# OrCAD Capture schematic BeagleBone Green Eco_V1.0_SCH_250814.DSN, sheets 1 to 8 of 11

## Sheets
1 P02_Block Diagram: rev: V1.0
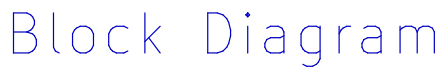
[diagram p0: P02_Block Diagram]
2 P01_Title, Revision History
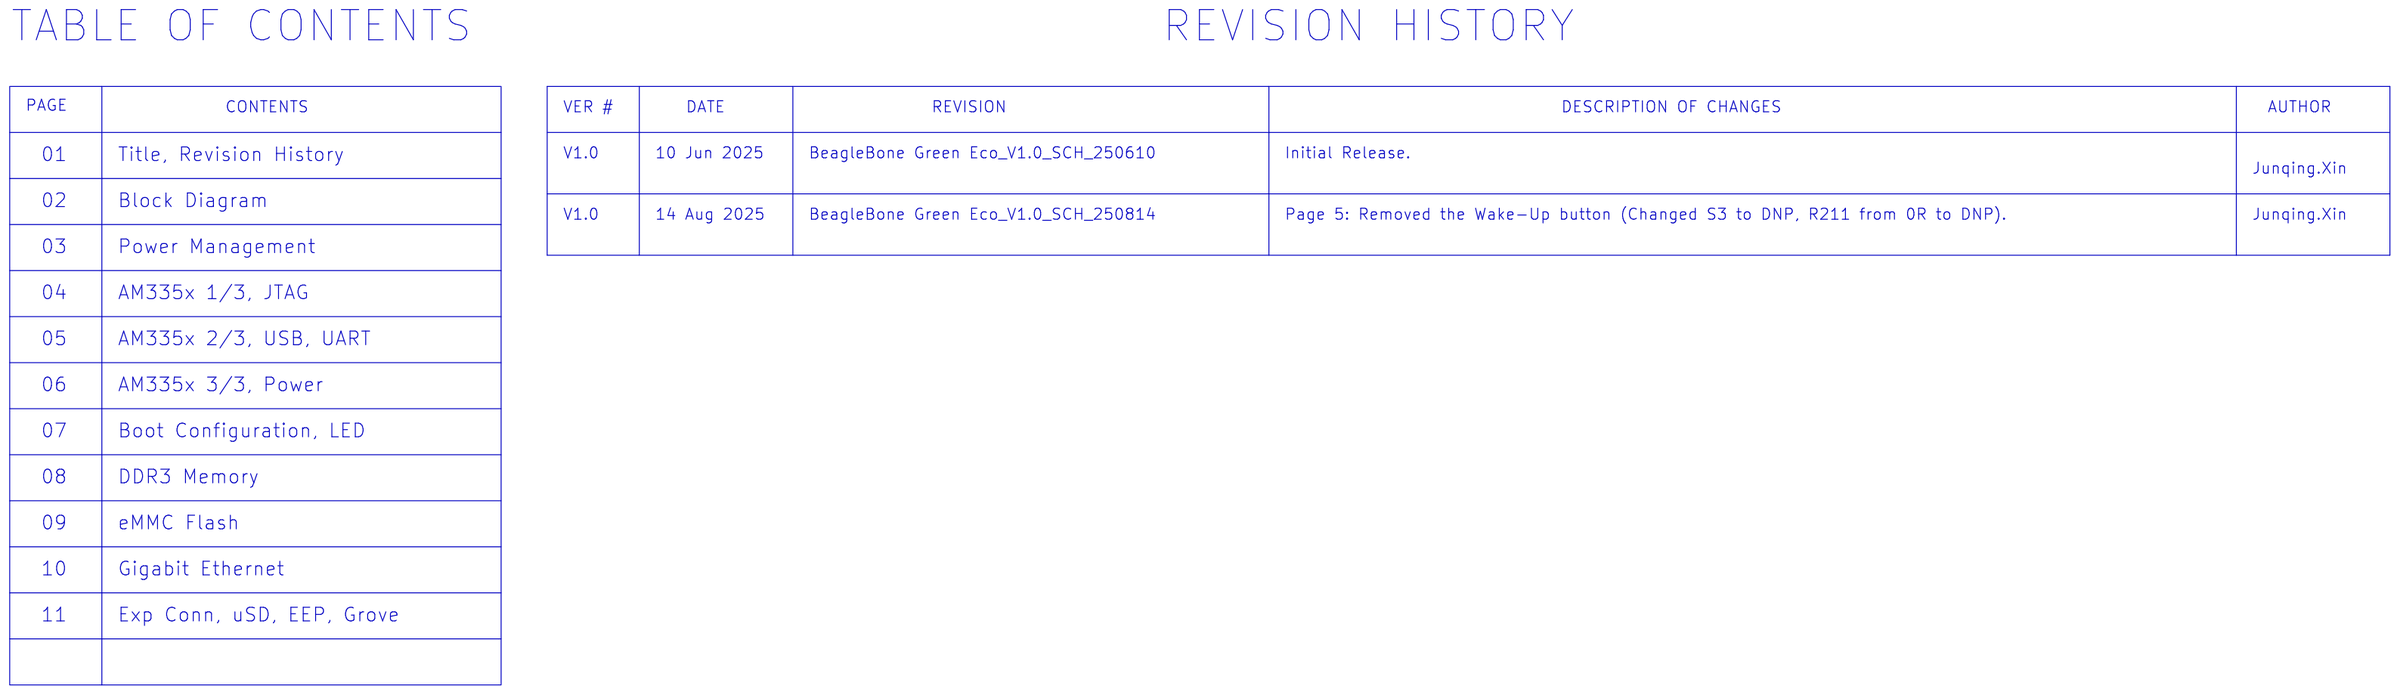
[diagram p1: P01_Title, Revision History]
3 P03_Power Management: size A3
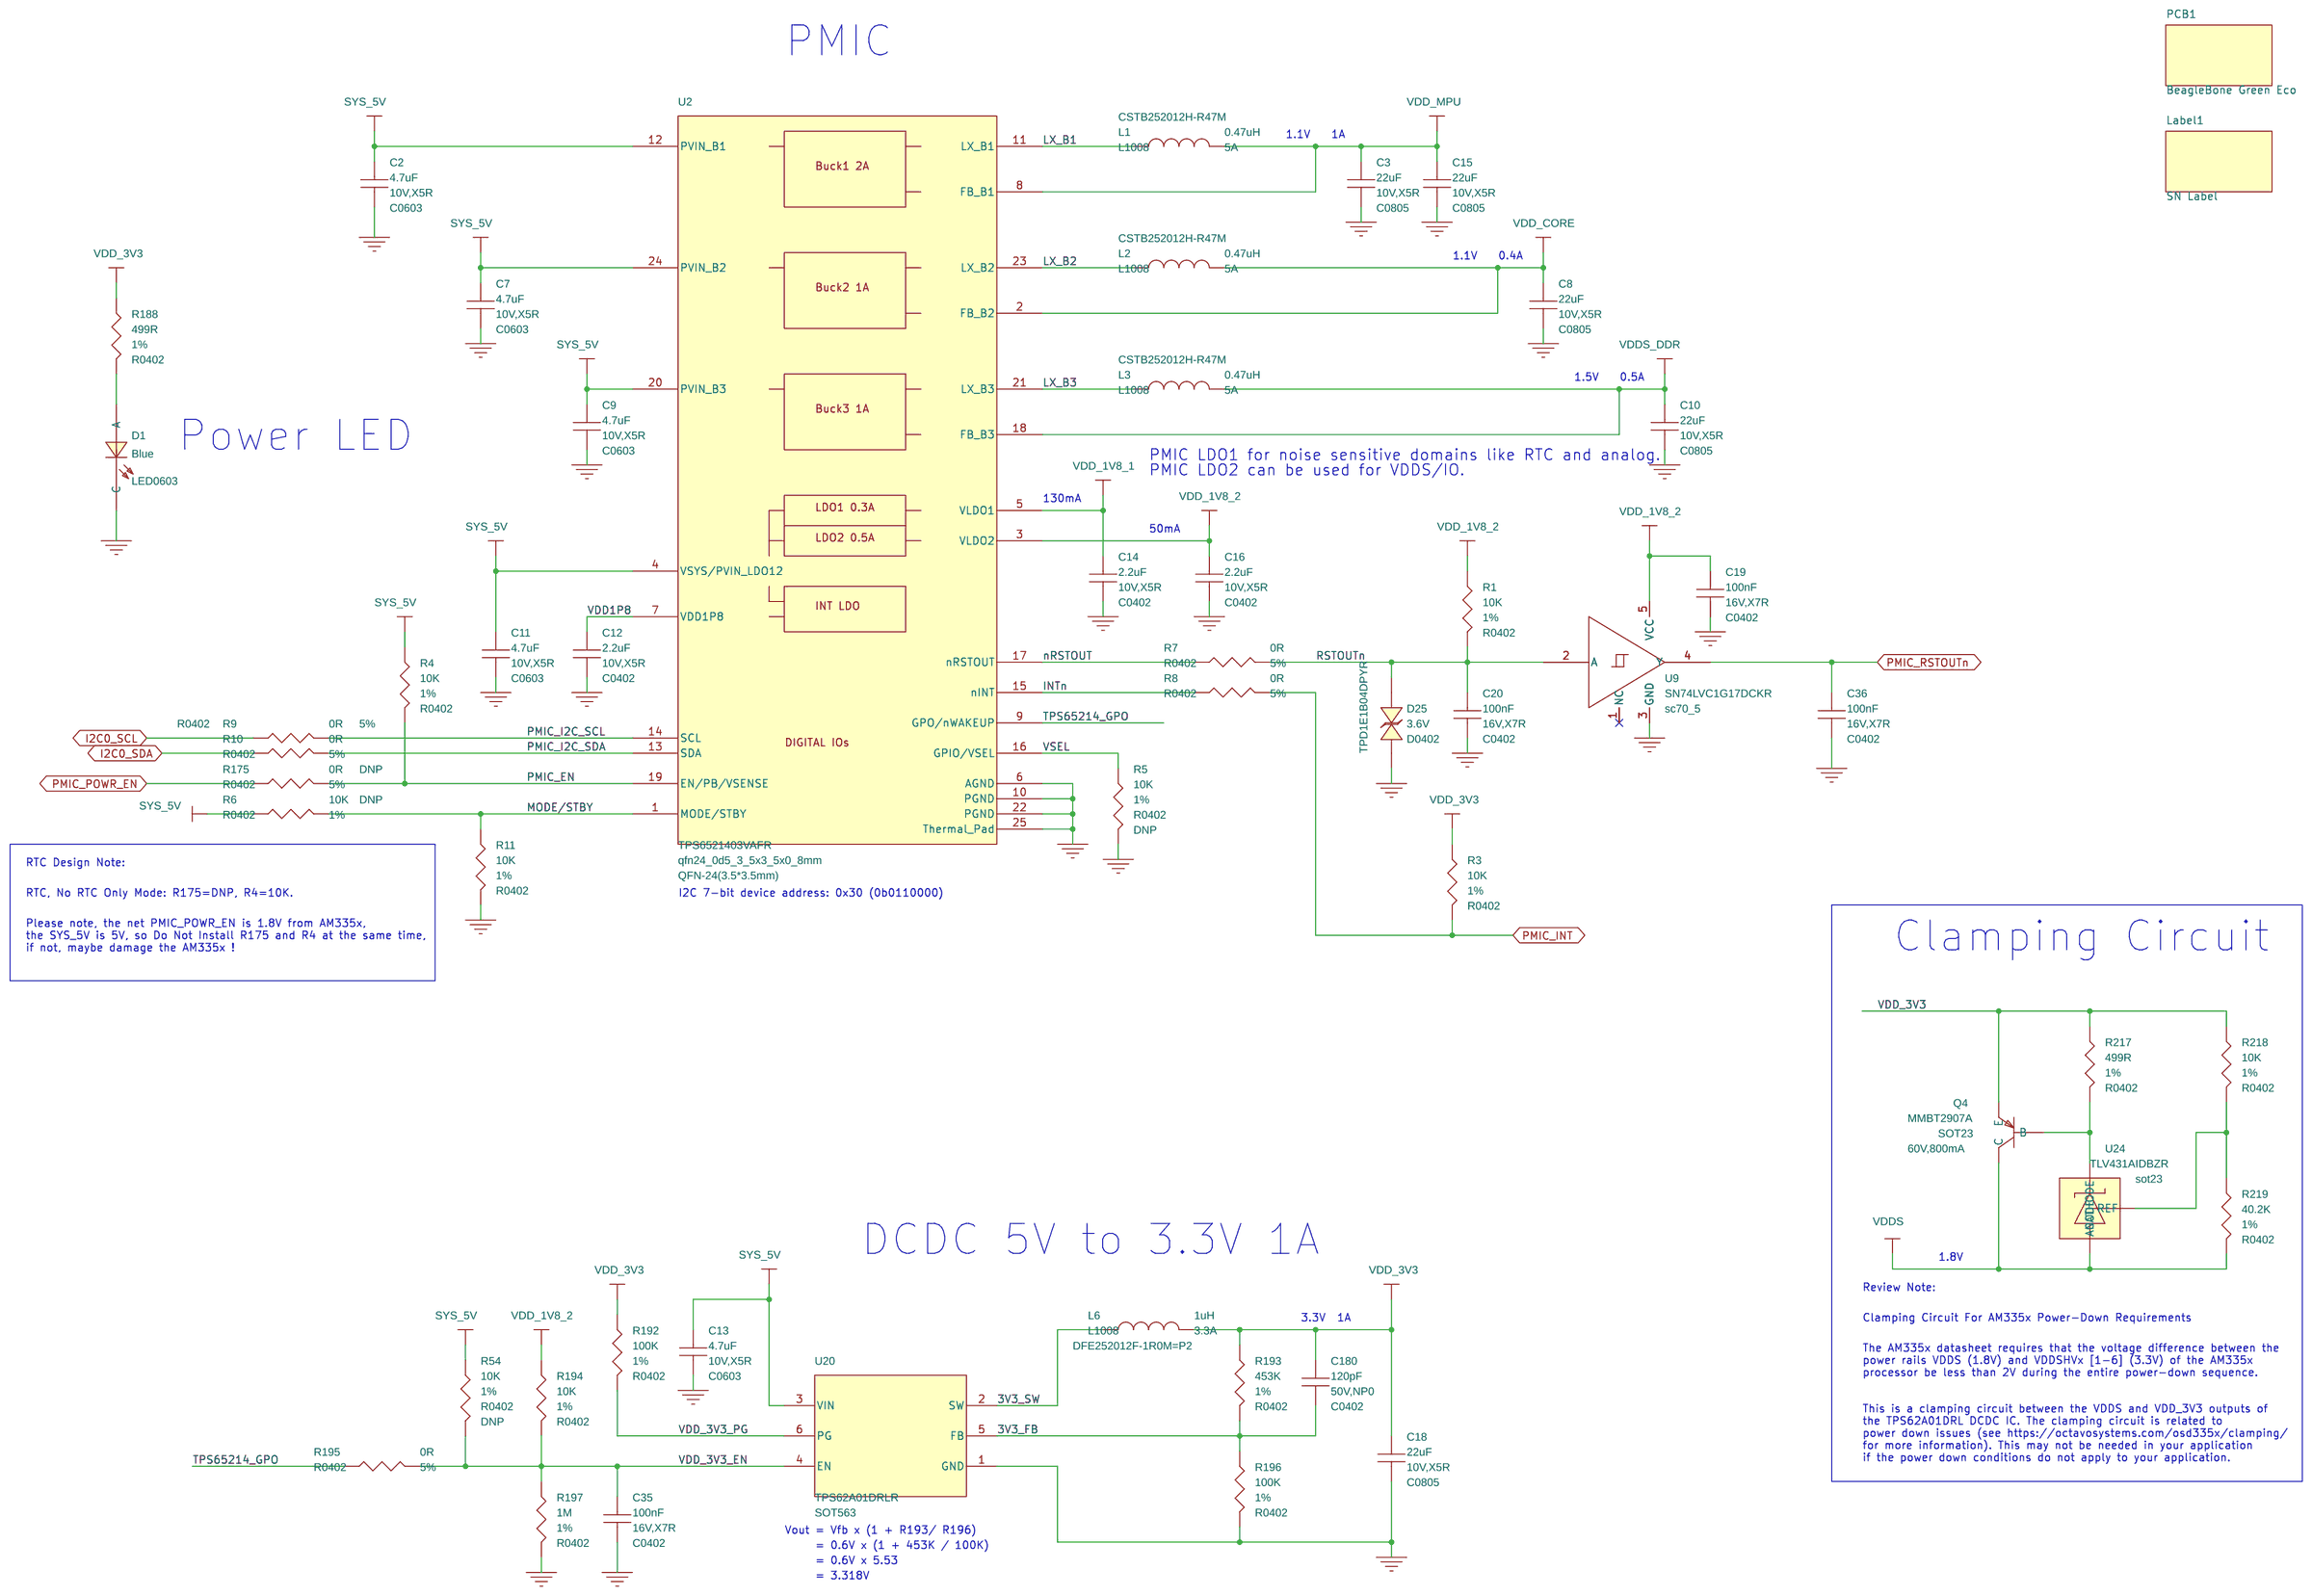
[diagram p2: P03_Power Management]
4 P07_Boot Configuration, LED: size A3
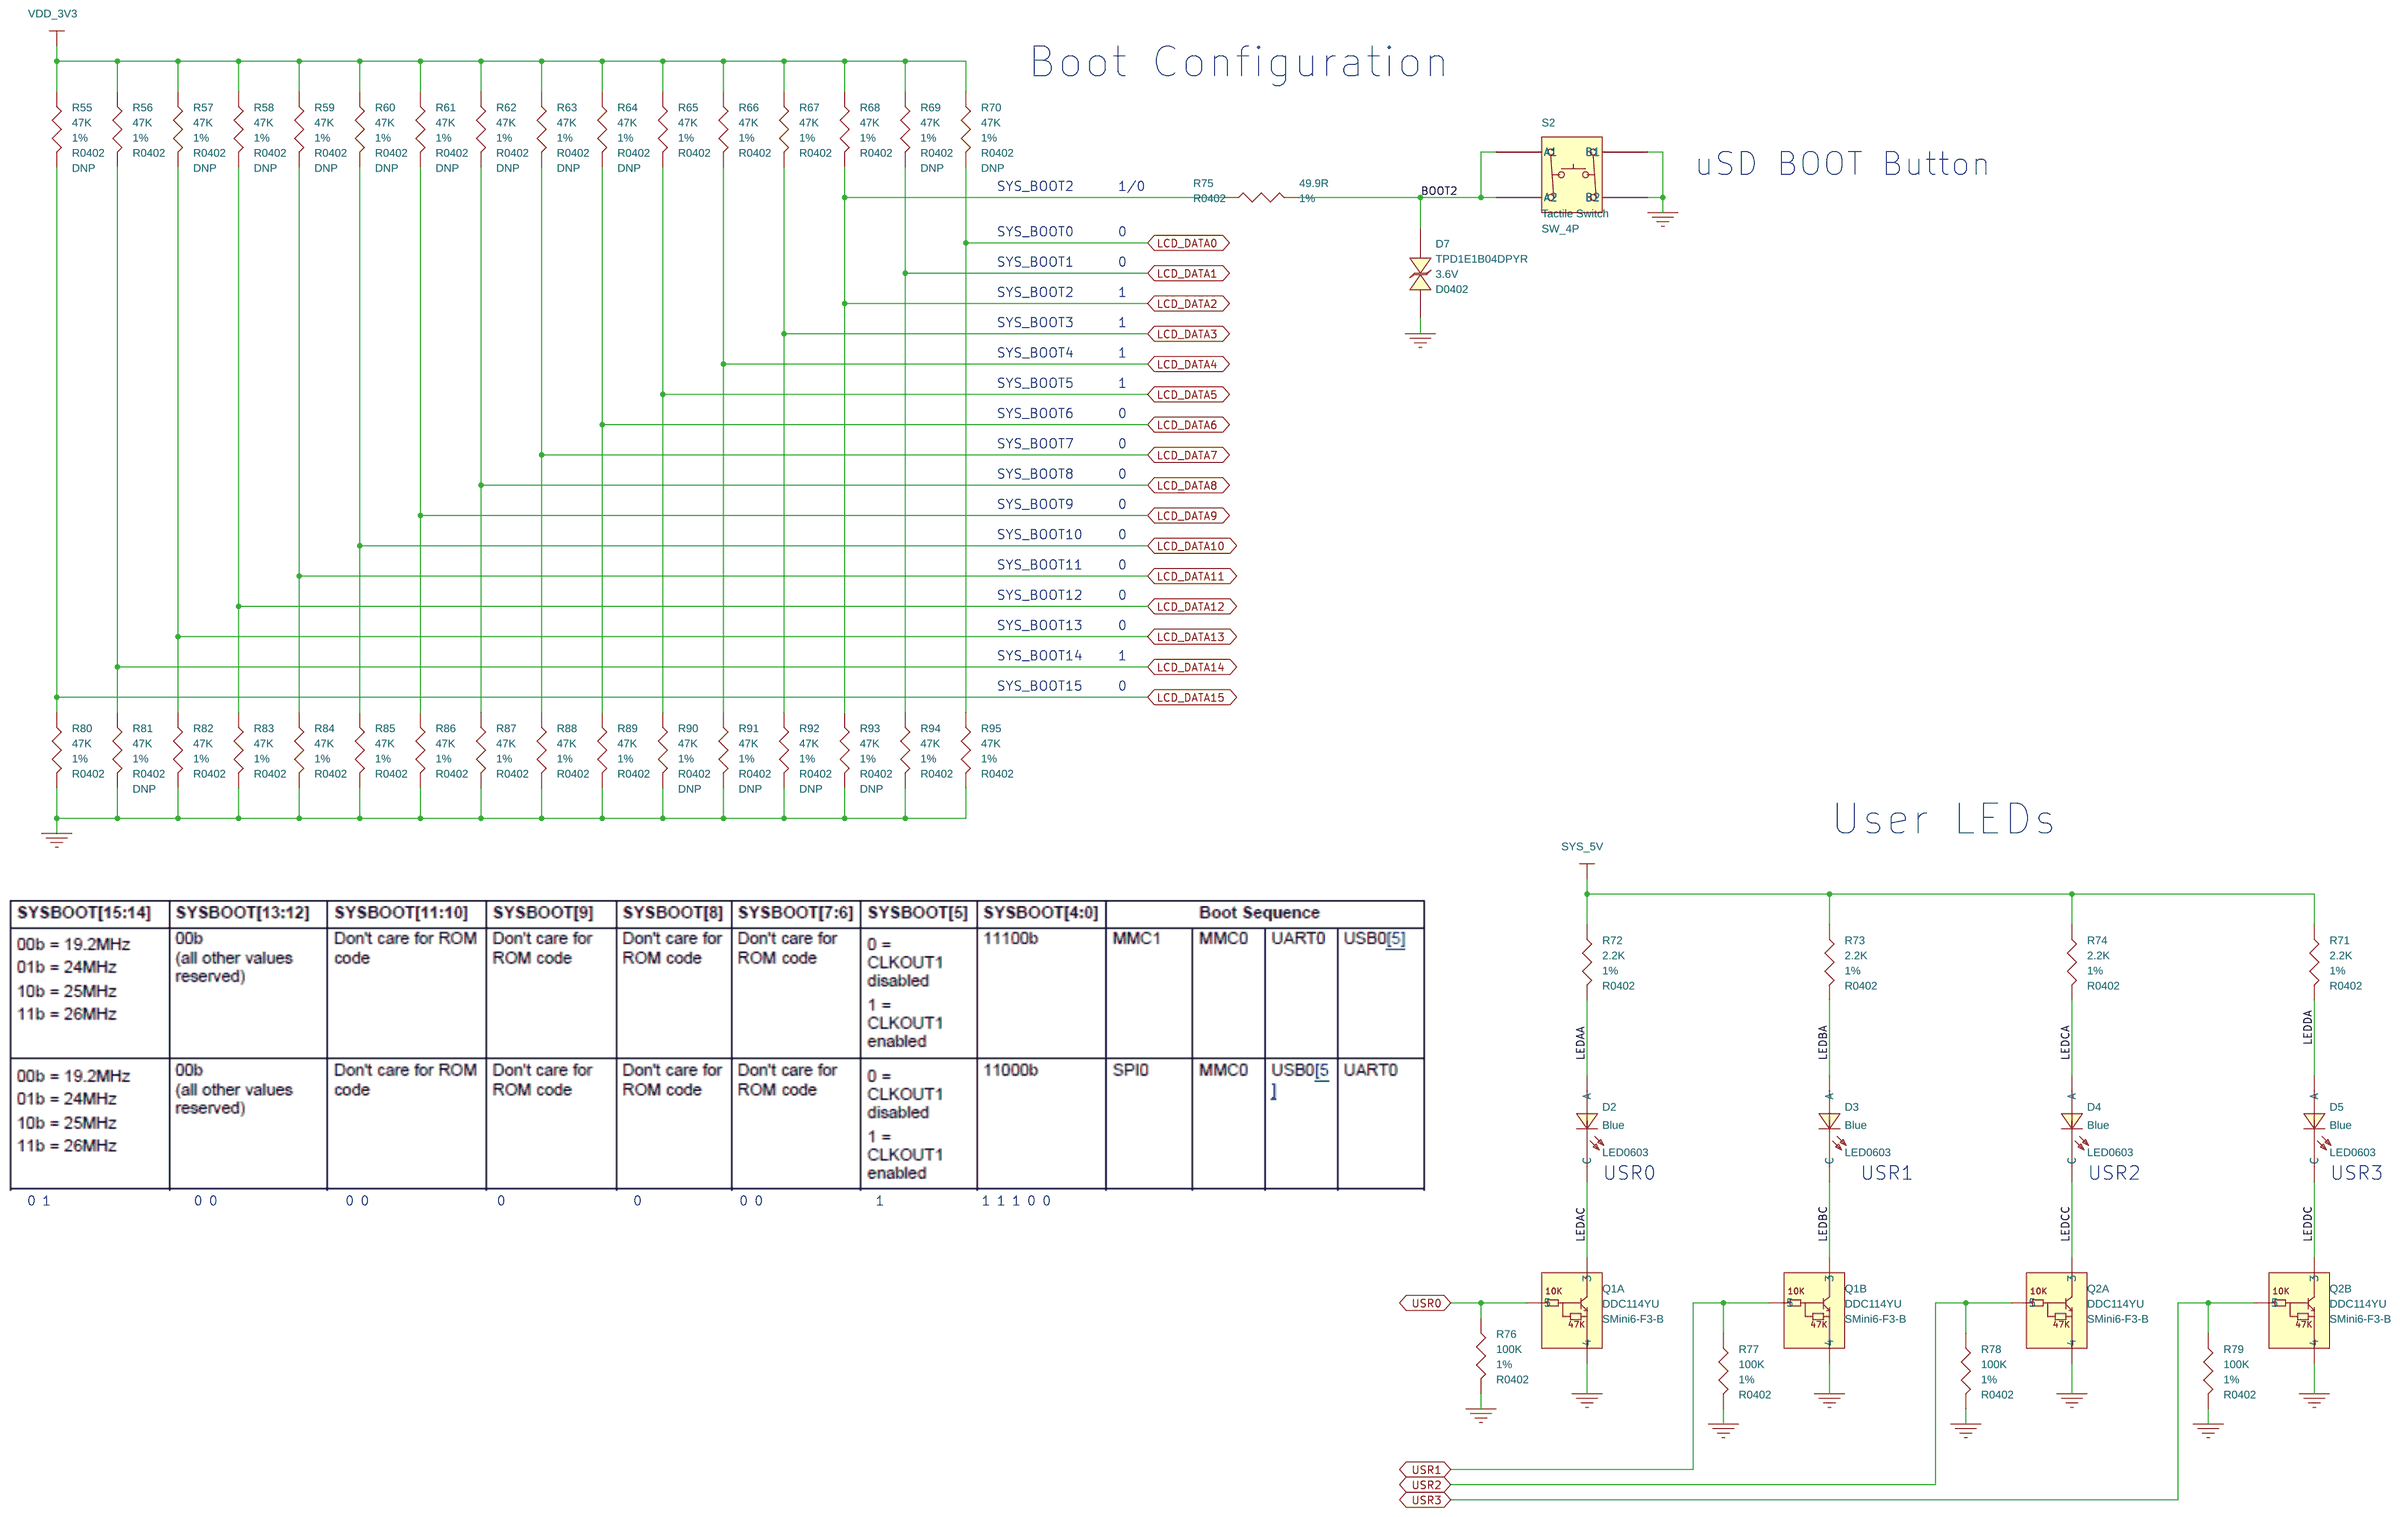
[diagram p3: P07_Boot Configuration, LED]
5 P08_DDR3 Memory: size A3
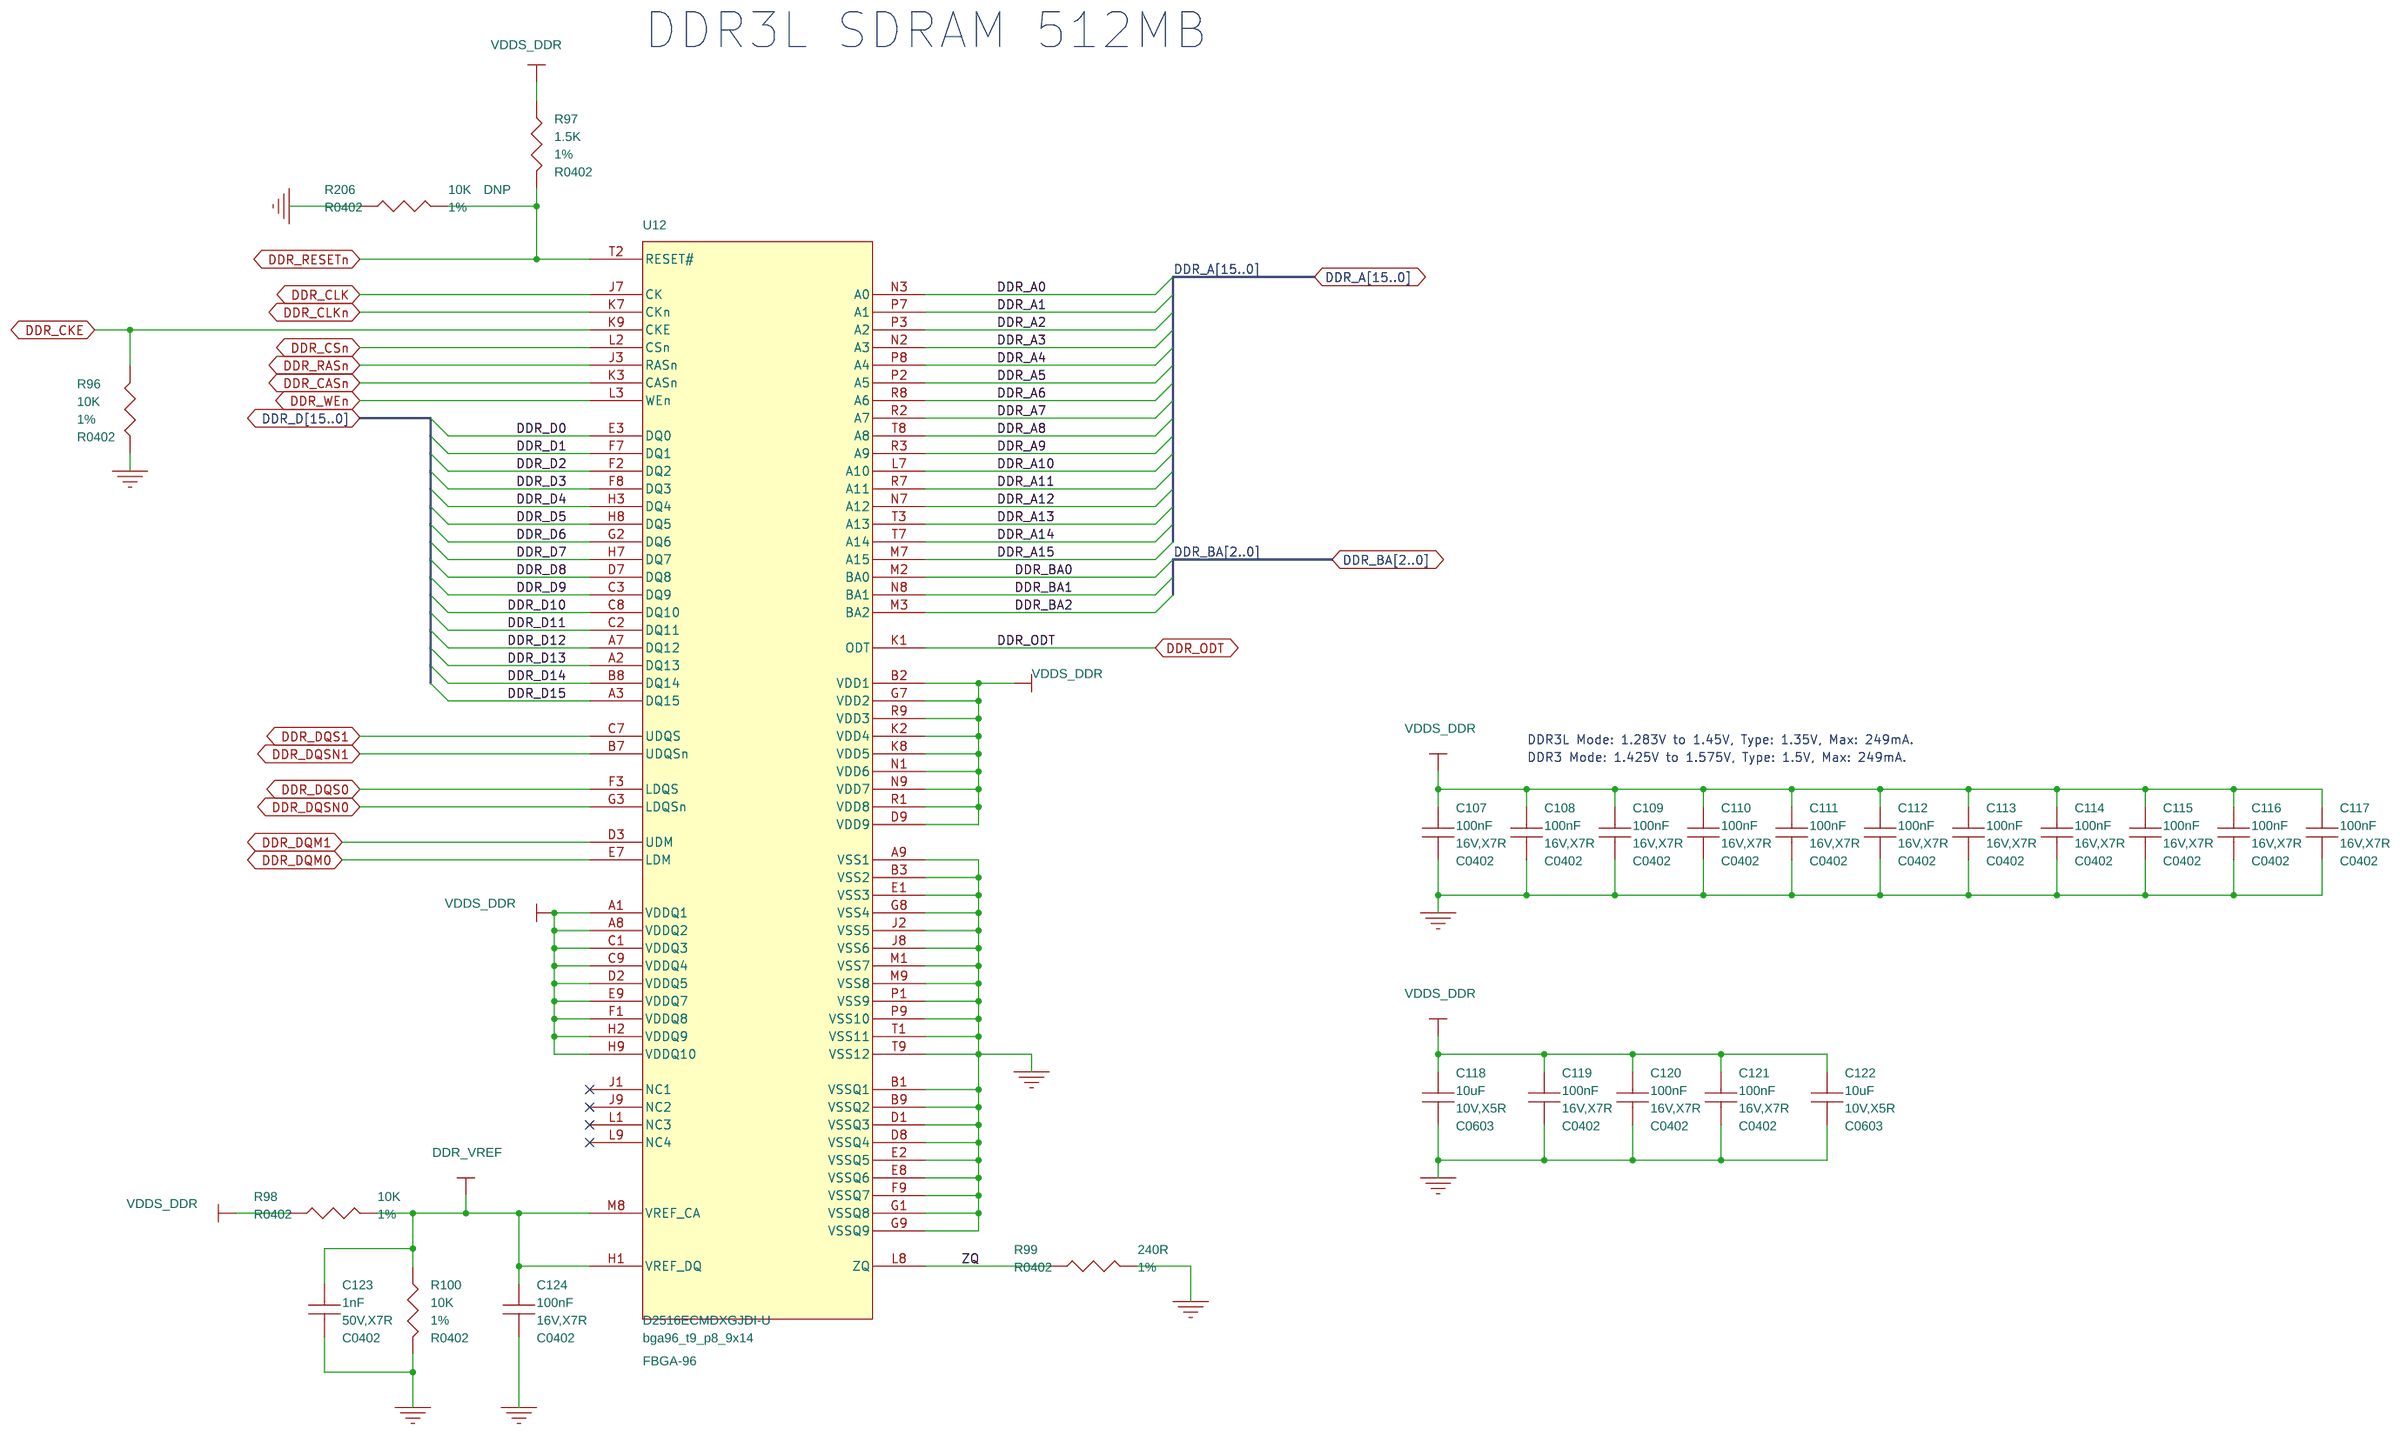
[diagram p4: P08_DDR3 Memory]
6 P09_eMMC Flash: size A3
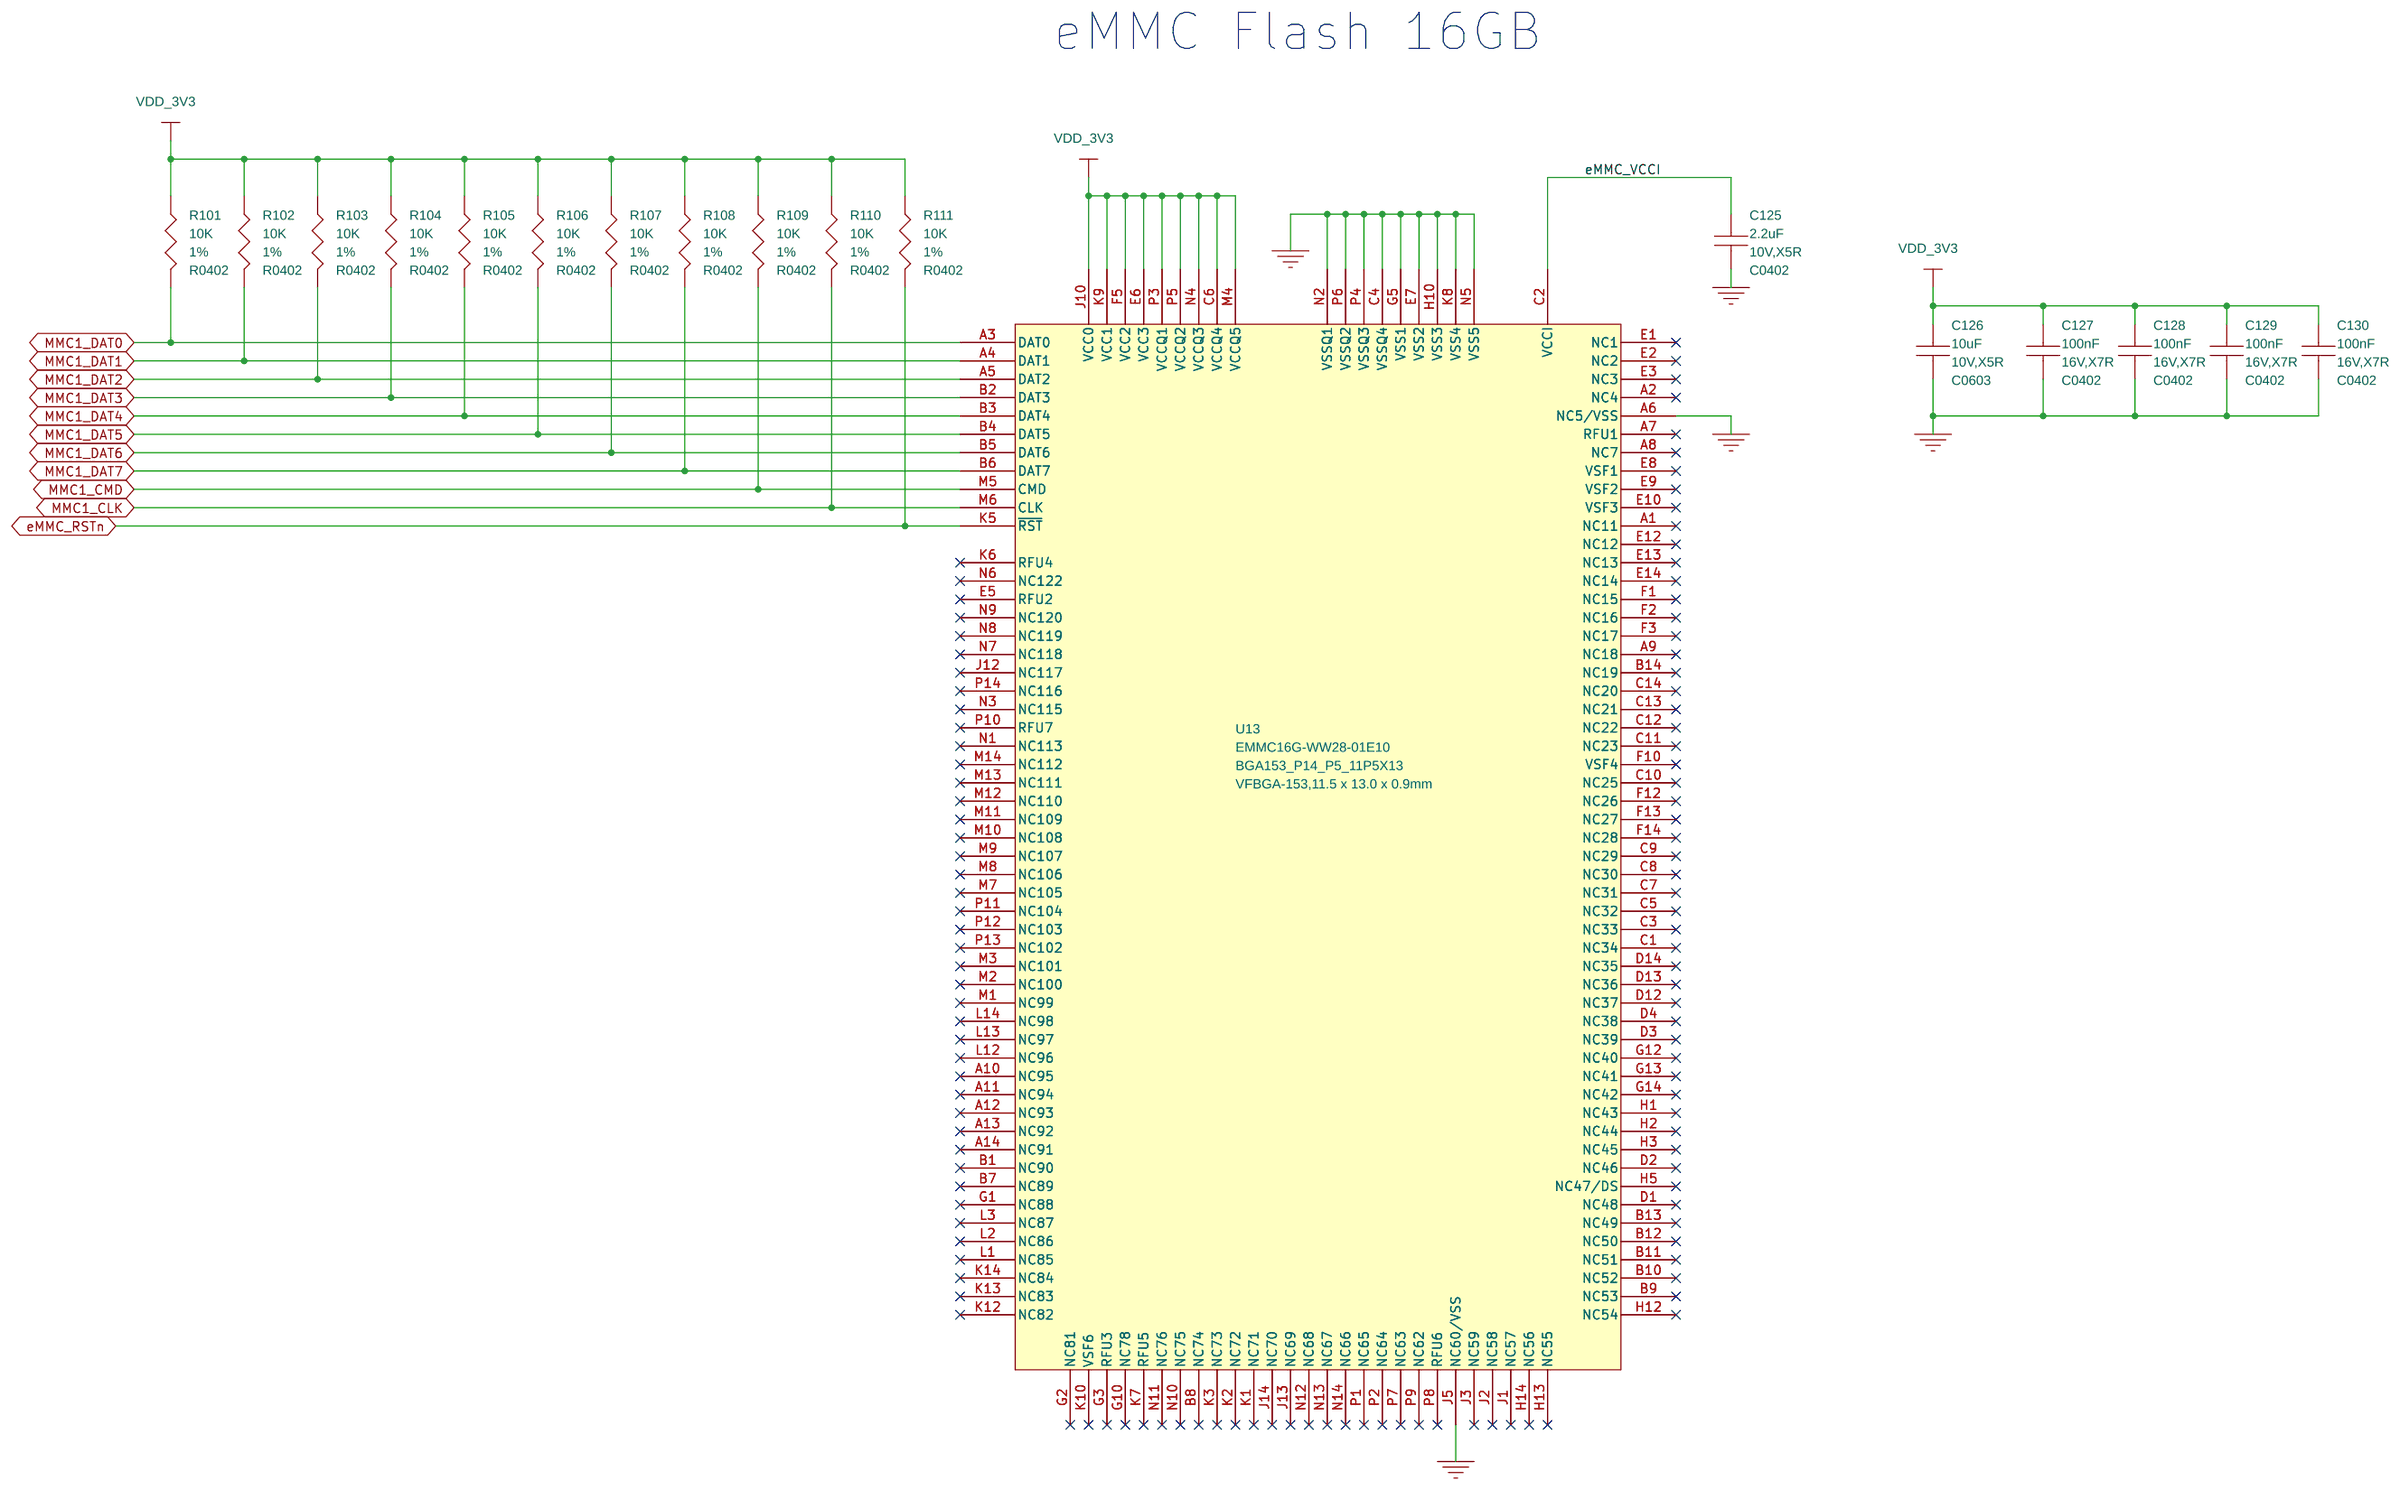
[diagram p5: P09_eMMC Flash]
7 P10_Gigabit Ethernet: size C
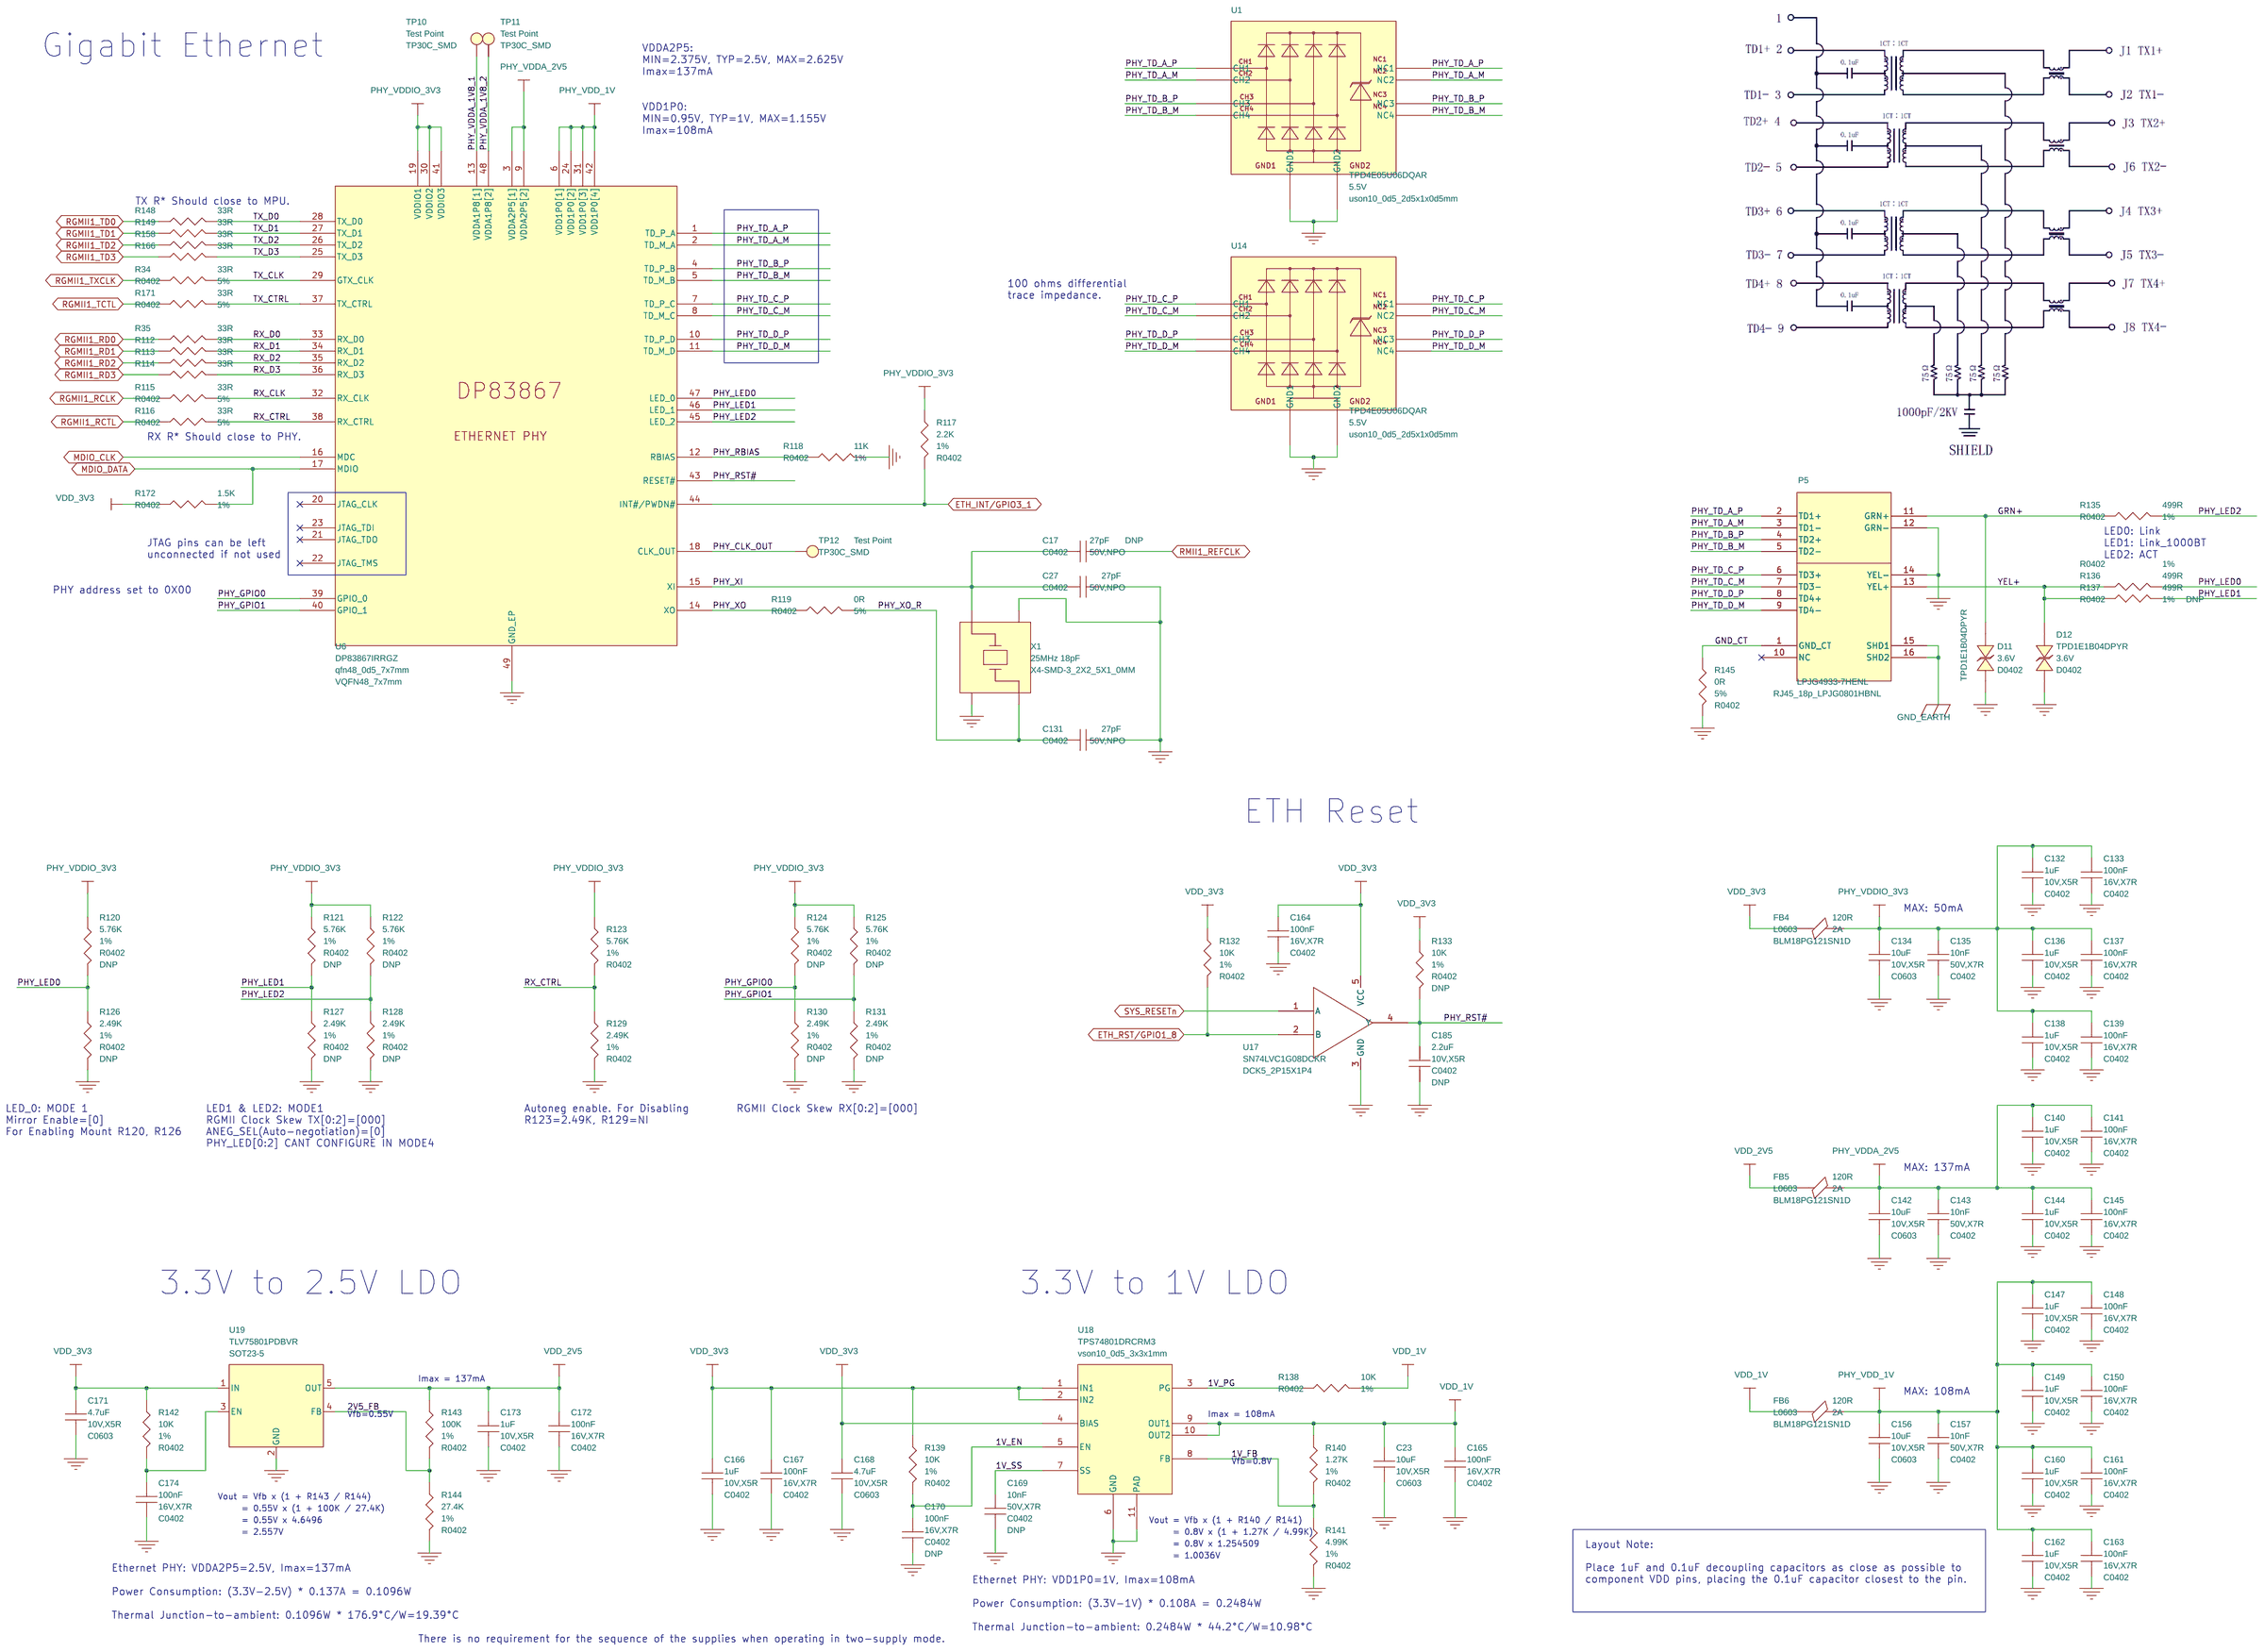
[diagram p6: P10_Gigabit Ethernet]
8 P11_Exp Conn, uSD, EEP, Grove: size A3
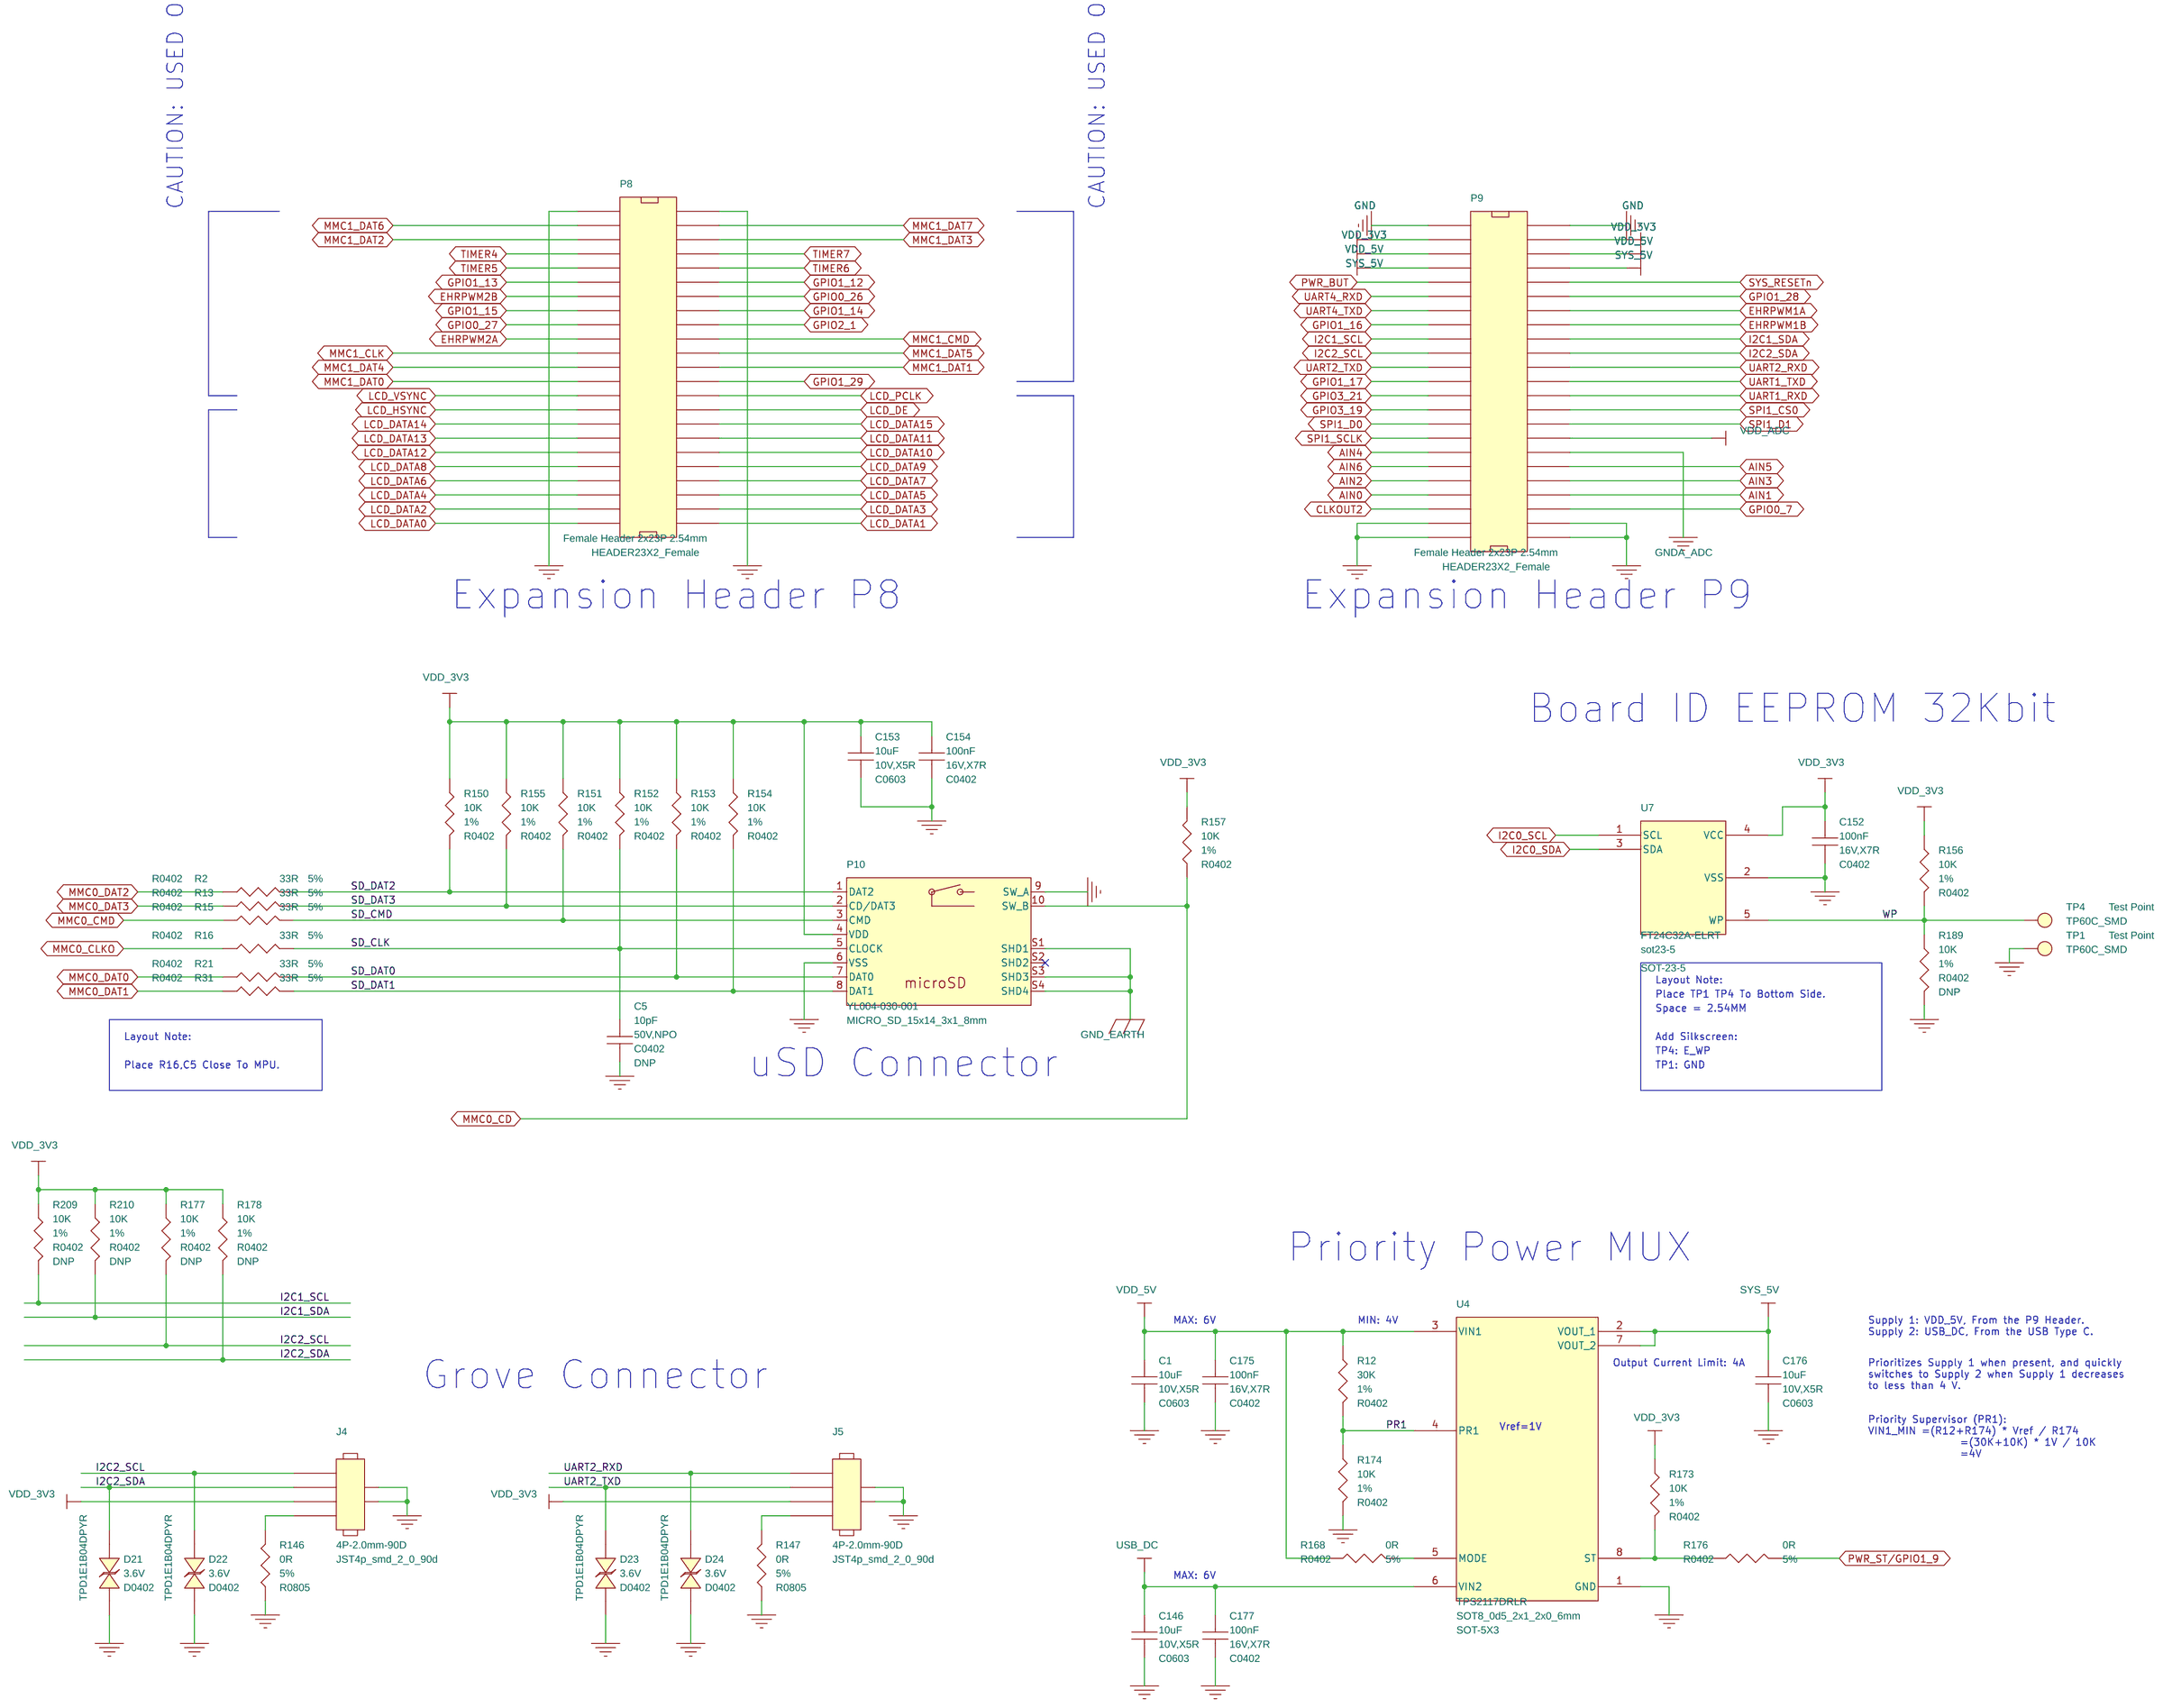
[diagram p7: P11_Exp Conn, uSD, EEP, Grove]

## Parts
sheet P03_Power Management
C2  4.7uF  [C0603]
C3  22uF  [C0805]
C7  4.7uF  [C0603]
C8  22uF  [C0805]
C9  4.7uF  [C0603]
C10  22uF  [C0805]
C11  4.7uF  [C0603]
C12  2.2uF  [C0402]
C13  4.7uF  [C0603]
C14  2.2uF  [C0402]
C15  22uF  [C0805]
C16  2.2uF  [C0402]
C18  22uF  [C0805]
C19  100nF  [C0402]
C20  100nF  [C0402]
C35  100nF  [C0402]
C36  100nF  [C0402]
C180  120pF  [C0402]
D1  Blue  [LED0603]
D25  TPD1E1B04DPYR  [D0402]
L1  0.47uH  [L1008]
L2  0.47uH  [L1008]
L3  0.47uH  [L1008]
L6  1uH  [L1008]
Label1  SN Label  [NA]
PCB1  BeagleBone Green Eco  [NA]
Q4  MMBT2907A  [SOT23]
R1  10K  [R0402]
R3  10K  [R0402]
R4  10K  [R0402]
R5  10K  [R0402]
R6  10K  [R0402]
R7  0R  [R0402]
R8  0R  [R0402]
R9  0R  [R0402]
R10  0R  [R0402]
R11  10K  [R0402]
R54  10K  [R0402]
R175  0R  [R0402]
R188  499R  [R0402]
R192  100K  [R0402]
R193  453K  [R0402]
R194  10K  [R0402]
R195  0R  [R0402]
R196  100K  [R0402]
R197  1M  [R0402]
R217  499R  [R0402]
R218  10K  [R0402]
R219  40.2K  [R0402]
U2  TPS6521403VAFR  [qfn24_0d5_3_5x3_5x0_8mm]
U9  SN74LVC1G17DCKR  [sc70_5]
U20  TPS62A01DRLR  [SOT563]
U24  TLV431AIDBZR  [sot23]
sheet P07_Boot Configuration, LED
D2  Blue  [LED0603]
D3  Blue  [LED0603]
D4  Blue  [LED0603]
D5  Blue  [LED0603]
D7  TPD1E1B04DPYR  [D0402]
Q1  DDC114YU  [SMini6-F3-B]  (sections A,B)
Q2  DDC114YU  [SMini6-F3-B]  (sections A,B)
R55  47K  [R0402]
R56  47K  [R0402]
R57  47K  [R0402]
R58  47K  [R0402]
R59  47K  [R0402]
R60  47K  [R0402]
R61  47K  [R0402]
R62  47K  [R0402]
R63  47K  [R0402]
R64  47K  [R0402]
R65  47K  [R0402]
R66  47K  [R0402]
R67  47K  [R0402]
R68  47K  [R0402]
R69  47K  [R0402]
R70  47K  [R0402]
R71  2.2K  [R0402]
R72  2.2K  [R0402]
R73  2.2K  [R0402]
R74  2.2K  [R0402]
R75  49.9R  [R0402]
R76  100K  [R0402]
R77  100K  [R0402]
R78  100K  [R0402]
R79  100K  [R0402]
R80  47K  [R0402]
R81  47K  [R0402]
R82  47K  [R0402]
R83  47K  [R0402]
R84  47K  [R0402]
R85  47K  [R0402]
R86  47K  [R0402]
R87  47K  [R0402]
R88  47K  [R0402]
R89  47K  [R0402]
R90  47K  [R0402]
R91  47K  [R0402]
R92  47K  [R0402]
R93  47K  [R0402]
R94  47K  [R0402]
R95  47K  [R0402]
S2  Tactile Switch  [SW_4P]
sheet P08_DDR3 Memory
C107  100nF  [C0402]
C108  100nF  [C0402]
C109  100nF  [C0402]
C110  100nF  [C0402]
C111  100nF  [C0402]
C112  100nF  [C0402]
C113  100nF  [C0402]
C114  100nF  [C0402]
C115  100nF  [C0402]
C116  100nF  [C0402]
C117  100nF  [C0402]
C118  10uF  [C0603]
C119  100nF  [C0402]
C120  100nF  [C0402]
C121  100nF  [C0402]
C122  10uF  [C0603]
C123  1nF  [C0402]
C124  100nF  [C0402]
R96  10K  [R0402]
R97  1.5K  [R0402]
R98  10K  [R0402]
R99  240R  [R0402]
R100  10K  [R0402]
R206  10K  [R0402]
U12  D2516ECMDXGJDI-U  [bga96_t9_p8_9x14]
sheet P09_eMMC Flash
C125  2.2uF  [C0402]
C126  10uF  [C0603]
C127  100nF  [C0402]
C128  100nF  [C0402]
C129  100nF  [C0402]
C130  100nF  [C0402]
R101  10K  [R0402]
R102  10K  [R0402]
R103  10K  [R0402]
R104  10K  [R0402]
R105  10K  [R0402]
R106  10K  [R0402]
R107  10K  [R0402]
R108  10K  [R0402]
R109  10K  [R0402]
R110  10K  [R0402]
R111  10K  [R0402]
U13  EMMC16G-WW28-01E10  [BGA153_P14_P5_11P5X13]
sheet P10_Gigabit Ethernet
C17  27pF  [C0402]
C23  10uF  [C0603]
C27  27pF  [C0402]
C131  27pF  [C0402]
C132  1uF  [C0402]
C133  100nF  [C0402]
C134  10uF  [C0603]
C135  10nF  [C0402]
C136  1uF  [C0402]
C137  100nF  [C0402]
C138  1uF  [C0402]
C139  100nF  [C0402]
C140  1uF  [C0402]
C141  100nF  [C0402]
C142  10uF  [C0603]
C143  10nF  [C0402]
C144  1uF  [C0402]
C145  100nF  [C0402]
C147  1uF  [C0402]
C148  100nF  [C0402]
C149  1uF  [C0402]
C150  100nF  [C0402]
C156  10uF  [C0603]
C157  10nF  [C0402]
C160  1uF  [C0402]
C161  100nF  [C0402]
C162  1uF  [C0402]
C163  100nF  [C0402]
C164  100nF  [C0402]
C165  100nF  [C0402]
C166  1uF  [C0402]
C167  100nF  [C0402]
C168  4.7uF  [C0603]
C169  10nF  [C0402]
C170  100nF  [C0402]
C171  4.7uF  [C0603]
C172  100nF  [C0402]
C173  1uF  [C0402]
C174  100nF  [C0402]
C185  2.2uF  [C0402]
D11  TPD1E1B04DPYR  [D0402]
D12  TPD1E1B04DPYR  [D0402]
FB4  120R  [L0603]
FB5  120R  [L0603]
FB6  120R  [L0603]
P5  LPJG4933-7HENL  [RJ45_18p_LPJG0801HBNL]
R34  33R  [R0402]
R35  33R  [R0402]
R112  33R  [R0402]
R113  33R  [R0402]
R114  33R  [R0402]
R115  33R  [R0402]
R116  33R  [R0402]
R117  2.2K  [R0402]
R118  11K  [R0402]
R119  0R  [R0402]
R120  5.76K  [R0402]
R121  5.76K  [R0402]
R122  5.76K  [R0402]
R123  5.76K  [R0402]
R124  5.76K  [R0402]
R125  5.76K  [R0402]
R126  2.49K  [R0402]
R127  2.49K  [R0402]
R128  2.49K  [R0402]
R129  2.49K  [R0402]
R130  2.49K  [R0402]
R131  2.49K  [R0402]
R132  10K  [R0402]
R133  10K  [R0402]
R135  499R  [R0402]
R136  499R  [R0402]
R137  499R  [R0402]
R138  10K  [R0402]
R139  10K  [R0402]
R140  1.27K  [R0402]
R141  4.99K  [R0402]
R142  10K  [R0402]
R143  100K  [R0402]
R144  27.4K  [R0402]
R145  0R  [R0402]
R148  33R  [R0402]
R149  33R  [R0402]
R158  33R  [R0402]
R166  33R  [R0402]
R171  33R  [R0402]
R172  1.5K  [R0402]
TP10  Test Point  [TP30C_SMD]
TP11  Test Point  [TP30C_SMD]
TP12  Test Point  [TP30C_SMD]
U1  TPD4E05U06DQAR  [uson10_0d5_2d5x1x0d5mm]
U6  DP83867IRRGZ  [qfn48_0d5_7x7mm]
U14  TPD4E05U06DQAR  [uson10_0d5_2d5x1x0d5mm]
U17  SN74LVC1G08DCKR  [DCK5_2P15X1P4]
U18  TPS74801DRCRM3  [vson10_0d5_3x3x1mm]
U19  TLV75801PDBVR  [SOT23-5]
X1  25MHz 18pF  [X4-SMD-3_2X2_5X1_0MM]
sheet P11_Exp Conn, uSD, EEP, Grove
C1  10uF  [C0603]
C5  10pF  [C0402]
C146  10uF  [C0603]
C152  100nF  [C0402]
C153  10uF  [C0603]
C154  100nF  [C0402]
C175  100nF  [C0402]
C176  10uF  [C0603]
C177  100nF  [C0402]
D21  TPD1E1B04DPYR  [D0402]
D22  TPD1E1B04DPYR  [D0402]
D23  TPD1E1B04DPYR  [D0402]
D24  TPD1E1B04DPYR  [D0402]
J4  4P-2.0mm-90D  [JST4p_smd_2_0_90d]
J5  4P-2.0mm-90D  [JST4p_smd_2_0_90d]
P8  Female Header 2x23P 2.54mm  [HEADER23X2_Female]
P9  Female Header 2x23P 2.54mm  [HEADER23X2_Female]
P10  YL004-030-001  [MICRO_SD_15x14_3x1_8mm]
R2  33R  [R0402]
R12  30K  [R0402]
R13  33R  [R0402]
R15  33R  [R0402]
R16  33R  [R0402]
R21  33R  [R0402]
R31  33R  [R0402]
R146  0R  [R0805]
R147  0R  [R0805]
R150  10K  [R0402]
R151  10K  [R0402]
R152  10K  [R0402]
R153  10K  [R0402]
R154  10K  [R0402]
R155  10K  [R0402]
R156  10K  [R0402]
R157  10K  [R0402]
R168  0R  [R0402]
R173  10K  [R0402]
R174  10K  [R0402]
R176  0R  [R0402]
R177  10K  [R0402]
R178  10K  [R0402]
R189  10K  [R0402]
R209  10K  [R0402]
R210  10K  [R0402]
TP1  Test Point  [TP60C_SMD]
TP4  Test Point  [TP60C_SMD]
U4  TPS2117DRLR  [SOT8_0d5_2x1_2x0_6mm]
U7  FT24C32A-ELRT  [sot23-5]

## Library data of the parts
C2 C7 C9 C11 C13 C168 C171 = CC: SMD CAP Ceramic 4.7uF-10V-10%-X5R;0603; Manufacturer: SAMSUNG; Manufacturer Part Number: CL10A475KP8NNNC; PN: 302013253; Package Size: 0603; Rating: 10V,X5R; Temperature: -55°C to 85°C
C3 C8 C10 C15 C18 = CC: SMD CAP Ceramic 22uF-10V-10%-X5R;0805; Manufacturer: Samsung; Manufacturer Part Number: CL21A226KPCLRNC; PN: 302012264; Package Size: 0805; Rating: 10V,X5R; Temperature: -55°C to 85°C
C12 C14 C16 C125 = CC: SMD CAP Ceramic 2.2uF-10V-10%-X5R;0402; Manufacturer: SAMSUNG; Manufacturer Part Number: CL05A225KP5NSNC; PN: 302013266; Package Size: 0402; Rating: 10V,X5R; Temperature: -55°C to 85°C
C19 C20 C35 C36 C107-C117 C119-C121 C124 C127-C130 C133 C137 C139 C141 C145 C148 C150 C152 C154 C161 C163-C165 C167 C172 C174 C175 C177 = CC: SMD CAP Ceramic 100nF-16V-10%-X7R;0402; Manufacturer: YAGEO; Manufacturer Part Number: CC0402KRX7R7BB104; PN: 302010004; Package Size: 0402; Rating: 16V,X7R; Temperature: -55°C to 125°C
C180 = CC: SMD CAP Ceramic 120pF-50V-5%-NP0;0402; Manufacturer: YAGEO; Manufacturer Part Number: CC0402JRNPO9BN121; PN: 302013487; Package Size: 0402; Rating: 50V,NP0; Temperature: -55°C to 125°C
D1-D5 = Single_LED: SMD LED Clear-Blue;0603; Manufacturer: Everlight; Manufacturer Part Number: 19-217/BHC-ZL1M2RY/6T; PN: 304090045; Package Size: 0603; Temperature: -40°C to 85°C
D7 D11 D12 D21-D25 = DIODE_TVS_BI-DIR: SMD TVS DIODE 3.6V-6.4V-1pF;X1SON(2); Manufacturer: TI; PN: 304050798; Package Size: 0402; Rating: 3.6V; Temperature: -40°C to 125°C
L1-L3 = L: SMD Inductor 0.47uH-20%-0.0215R-5.0A;2P-2520; CLASS: DISCRETE; Manufacturer: CODACA; Manufacturer Part Number: CSTB252012H-R47M; PN: 303011709; Package Size: 2520; Rating: 5A; Temperature: -40°C to 125°C
L6 = L: SMD Inductor 1uH-20%-3.3A;1008; Manufacturer: Murata; Manufacturer Part Number: DFE252012F-1R0M=P2; PN: 303010531; Package Size: 2520; Rating: 3.3A; Temperature: -40°C to 125°C
Label1 = PCB: Label;50# Bright White PET SN Label-L30*W7mm; PN: 327130435; Part Type: Label
PCB1 = PCB: PCB;BeagleBone Green Eco_V1.0-Green Soldermask,White Silkscreen-4 Layers; Manufacturer Part Number: 86*54*1.6mm-Immersion Gold-FR4; PN: 319016335
Q4 = PNP: SMD Transistor PNP 60V-800mA;SOT23-3; Manufacturer: Fairchild; PN: 305020037; Package Size: SOT23-3; Rating: 60V,800mA; Temperature: -55°C to 150°C
R1 R3 R4 R11 R96 R98 R100-R111 R132 R138 R139 R142 R150-R157 R173 R174 R194 R218 = R: SMD RES 10K-1%-1/16W;0402; Manufacturer: YAGEO; Manufacturer Part Number: RC0402FR-0710KL; PN: 301010047; Package Size: 0402; Rating: 1%; Temperature: -55°C to 155°C
R5 R6 R54 R133 R177 R178 R189 R206 R209 R210 = R: SMD RES 10K-1%-1/16W;0402; ASSY: DNP; Manufacturer: YAGEO; Manufacturer Part Number: RC0402FR-0710KL; PN: 301010047; Package Size: 0402; Rating: 1%; Temperature: -55°C to 155°C
R7-R10 R119 R145 R168 R176 R195 = R: SMD RES 0R-5%-1/16W;0402; Manufacturer: YAGEO; Manufacturer Part Number: RC0402JR-070RL; PN: 301010000; Package Size: 0402; Rating: 5%; Temperature: -55°C to 155°C
R175 = R: SMD RES 0R-5%-1/16W;0402; ASSY: DNP; Manufacturer: YAGEO; Manufacturer Part Number: RC0402JR-070RL; PN: 301010000; Package Size: 0402; Rating: 5%; Temperature: -55°C to 155°C
R135 R136 R188 R217 = R: SMD RES 499R-1%-1/16W;0402; Manufacturer: YAGEO; Manufacturer Part Number: RC0402FR-07499RL; PN: 301012386; Package Size: 0402; Rating: 1%; Temperature: -55°C to 155°C
R76-R79 R143 R192 R196 = R: SMD RES 100K-1%-1/16W;0402; Manufacturer: YAGEO; Manufacturer Part Number: RC0402FR-07100KL; PN: 301010456; Package Size: 0402; Rating: 1%; Temperature: -55°C to 155°C
R193 = R: SMD 453K-1%-1/16W-0402; Manufacturer: YAGEO; Manufacturer Part Number: RC0402FR-07453KL; PN: 301010670; Package Size: 0402; Rating: 1%; Temperature: -55°C to 155°C
R197 = R: SMD RES 1M-1%-1/16W;0402; Manufacturer: YAGEO; Manufacturer Part Number: RC0402FR-071ML; PN: 301010043; Package Size: 0402; Rating: 1%; Temperature: -55°C to 155°C
R219 = R: SMD RES 40.2K-1%-1/16W;0402; Manufacturer: YAGEO; Manufacturer Part Number: RC0402FR-0740K2L; PN: 301010062; Package Size: 0402; Rating: 1%; Temperature: -55°C to 155°C
U2 = TPS65214: SMD IC PMIC;3x DC-DC and 2x LDO, 2.5V to 5.5V, IIC interface;QFN-24(3.5*3.5mm); Manufacturer: TI; PN: 310033254; Package Size: QFN-24(3.5*3.5mm); Rating: 2.5V to 5.5V; Temperature: -40°C to 105°C
U9 = SN74AUP1T17DCKR: SMD IC Logic;Single Schmitt-Trigger Buffer-SC-70-5; Manufacturer: TI; PN: 310051133; Temperature: -40°C to 85°C
U20 = TPS62A06: SMD IC DCDC; Buck-2.5V to 5.5V-1A;SOT-563; Manufacturer: TI; PN: 310032692; Rating: 1A; Temperature: -40°C to 125°C
U24 = TLV431A: SMD IC PMIC; IC VREF SHUNT ADJ;SOT23-3; Manufacturer: TI; PN: 310031530; Package Size: SOT23-3; Temperature: -40°C to 85°C
Q1 Q2 = DDC114YU: SMD Transistor Array 2 NPN-50V-100mA-SOT-363; Manufacturer: Diodes; Manufacturer Part Number: DDC114YU-7-F; PN: 305050004; Package Size: SOT-363; Temperature: -55°C to 155°C
R55 R57-R64 R69 R70 R81 R90-R93 = R: SMD RES 47K-1%-1/16W;0402; ASSY: DNP; Manufacturer: YAGEO; Manufacturer Part Number: RC0402FR-0747KL; PN: 301010054; Package Size: 0402; Rating: 1%; Temperature: -55°C to 155°C
R56 R65-R68 R80 R82-R89 R94 R95 = R: SMD RES 47K-1%-1/16W;0402; Manufacturer: YAGEO; Manufacturer Part Number: RC0402FR-0747KL; PN: 301010054; Package Size: 0402; Rating: 1%; Temperature: -55°C to 155°C
R71-R74 R117 = R: SMD RES 2.2K-1%-1/16W;0402; Manufacturer: YAGEO; Manufacturer Part Number: RC0402FR-072K2L; PN: 301010746; Package Size: 0402; Rating: 1%; Temperature: -55°C to 155°C
R75 = R: SMD RES 49.9R-1%-1/16W;0402; Manufacturer: YAGEO; Manufacturer Part Number: RC0402FR-0749R9L; PN: 301010041; Package Size: 0402; Rating: 1%; Temperature: -55°C to 155°C
S2 = Tactile_Switch_4P: SMD Top Button 1.57N;4P-L4.6*W3.2*H2.5mm; Manufacturer: JinBeiLi Electrical; Manufacturer Part Number: TS-1185F-W; PN: 311021800; Package Size: 4.6 x 3.2 x 2.5mm; Temperature: -20°C to 70°C
C1 C23 C118 C122 C126 C134 C142 C146 C153 C156 C176 = CC: SMD CAP Ceramic 10uF-10V-10%-X5R;0603; Manufacturer: SAMSUNG; Manufacturer Part Number: CL10A106KP8NNNC; PN: 302013252; Package Size: 0603; Rating: 10V,X5R; Temperature: -55°C to 85°C
C123 = CC: SMD CAP Ceramic 1nF-50V-5%-X7R;0402; Manufacturer: YAGEO; Manufacturer Part Number: CC0402JRX7R9BB102; PN: 302010394; Package Size: 0402; Rating: 50V,X7R; Temperature: -55°C to 125°C
R97 R172 = R: SMD RES 1.5K-1%-1/16W;0402; Manufacturer: YAGEO; Manufacturer Part Number: RC0402FR-071K5L; PN: 301010567; Package Size: 0402; Rating: 1%; Temperature: -55°C to 155°C
R99 = R: SMD RES 240R-1%-1/16W;0402; Manufacturer: YAGEO; Manufacturer Part Number: RC0402FR-07240RL; PN: 301011475; Package Size: 0402; Rating: 1%; Temperature: -55°C to 155°C
U12 = DDR3_96-ball_FBGA: (BB) SMD IC Memory;DDR3-FBGA-96; Manufacturer: Kingston; PN: 310091067; Package Size: FBGA-96; Temperature: -40°C to 85°C
U13 = eMMC_5_1_153-ball_WFBGA: SMD IC Memory;16GB eMMC 5.1 HS400;VFBGA-153,11.5 x 13.0 x 0.9mm; Manufacturer: Kingston; PN: 310091844; Package Size: VFBGA-153,11.5 x 13.0 x 0.9mm; Rating: 16GB; Temperature: -40°C to 85°C
C17 = CC: SMD CAP Ceramic 27pF-50V-5%-NPO;0402; ASSY: DNP; Manufacturer: YAGEO; Manufacturer Part Number: CC0402JRNPO9BN270; PN: 302010027; Package Size: 0402; Part Type: Ceramic; Rating: 50V,NPO; Temperature: -55°C to 125°C
C27 C131 = CC: SMD CAP Ceramic 27pF-50V-5%-NPO;0402; Manufacturer: YAGEO; Manufacturer Part Number: CC0402JRNPO9BN270; PN: 302010027; Package Size: 0402; Part Type: Ceramic; Rating: 50V,NPO; Temperature: -55°C to 125°C
C132 C136 C138 C140 C144 C147 C149 C160 C162 C166 C173 = CC: SMD CAP Ceramic 1uF-10V-10%-X5R;0402; Manufacturer: Samsung; Manufacturer Part Number: CL05A105KP5NNNC; PN: 302013249; Package Size: 0402; Rating: 10V,X5R; Temperature: -55°C to 85°C
C135 C143 C157 = CC: SMD CAP Ceramic 10nF-50V-10%-X7R;0402; Manufacturer: YAGEO; Manufacturer Part Number: CC0402KRX7R9BB103; PN: 302010006; Package Size: 0402; Rating: 50V,X7R; Temperature: -55°C to 125°C
C169 = CC: SMD CAP Ceramic 10nF-50V-10%-X7R;0402; ASSY: DNP; Manufacturer: YAGEO; Manufacturer Part Number: CC0402KRX7R9BB103; PN: 302010006; Package Size: 0402; Rating: 50V,X7R; Temperature: -55°C to 125°C
C170 = CC: SMD CAP Ceramic 100nF-16V-10%-X7R;0402; ASSY: DNP; Manufacturer: YAGEO; Manufacturer Part Number: CC0402KRX7R7BB104; PN: 302010004; Package Size: 0402; Rating: 16V,X7R; Temperature: -55°C to 125°C
C185 = CC: SMD CAP Ceramic 2.2uF-10V-10%-X5R;0402; ASSY: DNP; Manufacturer: SAMSUNG; Manufacturer Part Number: CL05A225KP5NSNC; PN: 302013266; Package Size: 0402; Rating: 10V,X5R; Temperature: -55°C to 85°C
FB4-FB6 = FB: SMD Ferrite Bead;120R-2A;0603; Manufacturer: Murata; Manufacturer Part Number: BLM18PG121SN1D; PN: 303030024; Package Size: 0603; Rating: 2A; Temperature: -55°C to 125°C
P5 = RJ45_LPJG0933HENL: DIP RJ45;1000M,Integrated Magnetics,G/Y 2 LEDs,Right Angle,Voltage Type;16+2P-21.25*15.93*13.3mm; Manufacturer: LINK-PP; PN: 320140598; Package Size: 21.25*15.93*13.30mm; Temperature: -40°C to 85°C
R2 R13 R15 R16 R21 R31 R34 R35 R112-R116 R148 R149 R158 R166 R171 = R: SMD RES 33R-5%-1/16W;0402; Manufacturer: YAGEO; Manufacturer Part Number: RC0402JR-0733RL; PN: 301010034; Package Size: 0402; Rating: 5%; Temperature: -55°C to 155°C
R118 = R: SMD RES;11K-1%-1/16W-0402; Manufacturer: YAGEO; Manufacturer Part Number: RC0402FR-0711KL; PN: 301010568; Package Size: 0402; Part Type: RES; Rating: 1%; Temperature: -55°C to 155°C
R120-R122 R124 R125 = R: SMD RES 5.76K-1%-1/16W;0402; ASSY: DNP; Manufacturer: YAGEO; Manufacturer Part Number: RC0402FR-075K76L; PN: 301013075; Package Size: 0402; Part Type: RES; Rating: 1%; Temperature: -55°C to 155°C
R123 = R: SMD RES 5.76K-1%-1/16W;0402; Manufacturer: YAGEO; Manufacturer Part Number: RC0402FR-075K76L; PN: 301013075; Package Size: 0402; Part Type: RES; Rating: 1%; Temperature: -55°C to 155°C
R126-R128 R130 R131 = R: SMD RES 2.49K-1%-1/16W;0402; ASSY: DNP; Manufacturer: YAGEO; Manufacturer Part Number: RC0402FR-072K49L; PN: 301010856; Package Size: 0402; Part Type: RES; Rating: 1%; Temperature: -55°C to 155°C
R129 = R: SMD RES 2.49K-1%-1/16W;0402; Manufacturer: YAGEO; Manufacturer Part Number: RC0402FR-072K49L; PN: 301010856; Package Size: 0402; Part Type: RES; Rating: 1%; Temperature: -55°C to 155°C
R137 = R: SMD RES 499R-1%-1/16W;0402; ASSY: DNP; Manufacturer: YAGEO; Manufacturer Part Number: RC0402FR-07499RL; PN: 301012386; Package Size: 0402; Rating: 1%; Temperature: -55°C to 155°C
R140 = R: SMD RES 1.27K-1%-1/16W;0402; Manufacturer: YAGEO; Manufacturer Part Number: RC0402FR-071K27L; PN: 301012748; Package Size: 0402; Rating: 1%; Temperature: -55°C to 155°C
R141 = R: SMD RES;4.99K-1/16W-1%-0402; Manufacturer: YAGEO; Manufacturer Part Number: RC0402FR-074K99L; PN: 301010572; Package Size: 0402; Part Type: RES; Priority: A; Rating: 1%; Temperature: -55°C to 155°C
R144 = R: SMD RES 27.4K-1%-1/16W;0402; Manufacturer: YAGEO; Manufacturer Part Number: RC0402FR-0727K4L; PN: 301013908; Package Size: 0402; Rating: 1%; Temperature: -55°C to 155°C
TP10-TP12 = Test_Point: Test Point;TP30C_SMD
U1 U14 = TPD4E05U06DQAR: SMD Diode Array ESD;4 Channel,6 Gbps,5.5V;USON-10; Manufacturer: TI; PN: 304060294; Package Size: USON-10; Part Type: ESD; Priority: A; Rating: 5.5V; Temperature: -40°C to 125°C
U6 = DP83867CRRGZ: SMD IC PHY;10/100/1000 Ethernet Physical Layer Transceiver;VQFN-48; Manufacturer: TI; Manufacturer Part Number: DP83867IRRGZR; PN: 310071487; Package Size: VQFN48_7x7mm; Part Type: Transceiver; Priority: A; Rating: 1000Mbps; Temperature: -40°C to 85°C
U17 = SN74LVC1G08DCKR: SMD IC Logic;Single 2-Input Positive-AND Gate;SC70-5; Manufacturer: TI; PN: 310050811; Package Size: SC-70-5; Part Type: Buffer; Temperature: -40°C to 125°C
U18 = TPS74801DRCR: SMD IC PMIC;LDO-ADJ-1.5A;VSON-10; Manufacturer: TI; PN: 310032838; Package Size: VSON-10; Part Type: LDO; Priority: A; Rating: 1.5A; Temperature: -40°C to 125°C
U19 = LDO_5P_FB_EN: SMD IC PMIC;LDO-ADJ-500mA;SOT23-5; Manufacturer: TI; PN: 310032000; Rating: 500mA; Temperature: -40°C to 125°C
X1 = XTAL_4P: SMD Crystal 25MHz-18pF-20ppm;4P-SMD-L3.2*W2.5*H0.8mm; Manufacturer: Interquip; Manufacturer Part Number: 5YAA25000182TF40Q3; PN: 306011192; Package Size: 3.2x2.5mm; Part Type: Crystal; Rating: 20ppm,18pF; Temperature: -40°C to 85°C
C5 = CC: SMD CAP Ceramic 10pF-50V-5%-NPO;0402; ASSY: DNP; Manufacturer: YAGEO; Manufacturer Part Number: CC0402JRNPO9BN100; PN: 302010001; Package Size: 0402; Rating: 50V,NPO; Temperature: -55°C to 125°C
J4 J5 = Header_4+2P: SMD Grove Female Header-Beige;4P-2.0-90D; Manufacturer: SINOTOP Electronics; Manufacturer Part Number: PHS-4A 90D; PN: 320110032; Package Size: 4P-2.0-90D
P8 P9 = Header_2x23: DIP Black Female Header;2*23P-2.54*8.5-3.0mm; Manufacturer: SINOTOP Electronics; Manufacturer Part Number: FF-1236; PN: 320030424; Package Size: 2*23P-2.54*8.5-3.0mm; Rating: 2x23Pin; Temperature: -40°C to 105°C
P10 = MicroSD_Card_10+4P: SMD SD Card Holder;Reverse-Bottom,8P-14.3*16mm; Manufacturer: Yuliang Electronics; PN: 320090416; Package Size: 4P+6-L15*W14*H1.8mm; Part Type: SD Card; Temperature: -20°C to 85°C
R12 = R: SMD RES 30K-1%-1/16W;0402; Manufacturer: YAGEO; Manufacturer Part Number: RC0402FR-0730KL; PN: 301010048; Package Size: 0402; Rating: 1%; Temperature: -55°C to 155°C
R146 R147 = R: SMD RES 0R-5%-1/8W;0805; Manufacturer: YAGEO; Manufacturer Part Number: RC0805JR-070RL; PN: 301010359; Package Size: 0805; Rating: 5%; Temperature: -55°C to 155°C
TP1 TP4 = Test_Point: Test Point;TP60C_SMD; Temperature: NA
U4 = TPS2117: SMD IC Priority Power MUX;1.6V-5.5V 4A;SOT-5X3; Manufacturer: TI; PN: 310033255; Package Size: SOT-5X3; Rating: 1.6V-5.5V, 4A; Temperature: -40°C to 125°C
U7 = MEM_24LC32_SOT23-5: SMD IC Memory;32Kb-IIC Serial EEPROM;SOT23-5; Manufacturer: FMD; PN: 310091347; Package Size: SOT-23-5; Temperature: -40°C to 85°C

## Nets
1V_EN: C170.1 R139.2 U18.5(EN)
1V_FB: R140.2 R141.1 U18.8(FB)
1V_PG: R138.1 U18.3(PG)
1V_SS: C169.1 U18.7(SS)
2V5_FB: R143.2 R144.1 U19.4(FB)
3V3_FB: C180.2 R193.2 R196.1 U20.5(FB)
3V3_SW: L6.1 U20.2(SW)
GND: C1.2 C2.2 C3.2 C5.2 C7.2 C8.2 C9.2 C10.2 C11.2 C12.2 C13.2 C14.2 C15.2 C16.2 C18.2 C19.2 C20.2 C23.2 C27.2 C35.2 C36.2 C107.2 C108.2 C109.2 C110.2 C111.2 C112.2 C113.2 C114.2 C115.2 C116.2 C117.2 C118.2 C119.2 C120.2 C121.2 C122.2 C123.2 C124.2 C125.2 C126.2 C127.2 C128.2 C129.2 C130.2 C131.2 C132.2 C133.2 C134.2 C135.2 C136.2 C137.2 C138.2 C139.2 C140.2 C141.2 C142.2 C143.2 C144.2 C145.2 C146.2 C147.2 C148.2 C149.2 C150.2 C152.2 C153.2 C154.2 C156.2 C157.2 C160.2 C161.2 C162.2 C163.2 C164.2 C165.2 C166.2 C167.2 C168.2 C169.2 C170.2 C171.2 C172.2 C173.2 C174.2 C175.2 C176.2 C177.2 C185.2 D1.2(C) D7.1 D11.1 D12.1 D21.1 D22.1 D23.1 D24.1 D25.1 J4.5 J4.6 J5.5 J5.6 P5.12(GRN-) P5.14(YEL-) P8.1 P8.2 P9.1 P9.2 P9.43 P9.44 P9.45 P9.46 P10.6(VSS) P10.9(SW_A) Q1.1(4) Q1.4 Q2.1(4) Q2.4 R5.2 R11.2 R76.2 R77.2 R78.2 R79.2 R80.2 R81.2 R82.2 R83.2 R84.2 R85.2 R86.2 R87.2 R88.2 R89.2 R90.2 R91.2 R92.2 R93.2 R94.2 R95.2 R96.1 R99.2 R100.2 R118.2 R126.2 R127.2 R128.2 R129.2 R130.2 R131.2 R141.2 R144.2 R145.2 R146.1 R147.1 R174.2 R189.2 R196.2 R197.2 R206.1 S2.2(B1) S2.4(B2) TP1.1(TP) U1.3(GND1) U1.8(GND2) U2.6(AGND) U2.10(PGND) U2.22(PGND) U2.25(Thermal_Pad) U4.1(GND) U6.49(GND_EP) U7.2(VSS) U9.3(GND) U12.A9(VSS1) U12.B1(VSSQ1) U12.B3(VSS2) U12.B9(VSSQ2) U12.D1(VSSQ3) U12.D8(VSSQ4) U12.E1(VSS3) U12.E2(VSSQ5) U12.E8(VSSQ6) U12.F9(VSSQ7) U12.G1(VSSQ8) U12.G8(VSS4) U12.G9(VSSQ9) U12.J2(VSS5) U12.J8(VSS6) U12.M1(VSS7) U12.M9(VSS8) U12.P1(VSS9) U12.P9(VSS10) U12.T1(VSS11) U12.T9(VSS12) U13.A6(NC5/VSS) U13.C4(VSSQ4) U13.E7(VSS2) U13.G5(VSS1) U13.H10(VSS3) U13.J5(NC60/VSS) U13.K8(VSS4) U13.N2(VSSQ1) U13.N5(VSS5) U13.P4(VSSQ3) U13.P6(VSSQ2) U14.3(GND1) U14.8(GND2) U17.3(GND) U18.6(GND) U18.11(PAD) U19.2(GND) U20.1(GND) X1.2 X1.4 ; also on sheet 9 10 11
GND_CT: P5.1(GND_CT) R145.1
GND_EARTH: P5.15(SHD1) P5.16(SHD2) P10.S1(SHD1) P10.S3(SHD3) P10.S4(SHD4) ; also on sheet 10
GNDA_ADC: P9.34 ; also on sheet 10 11
VDD1P8: C12.1 U2.7(VDD1P8)
VDD_1V: C23.1 C165.1 FB6.1 R138.2 R140.1 U18.9(OUT1) U18.10(OUT2)
VDD_1V8_1: C14.1 U2.5(VLDO1) ; also on sheet 11
VDD_1V8_2: C16.1 C19.1 R1.1 R194.1 U2.3(VLDO2) U9.5(VCC) ; also on sheet 9 10 11
VDD_2V5: C172.1 C173.1 FB5.1 R143.1 U19.5(OUT)
VDD_3V3: C18.1 C126.1 C127.1 C128.1 C129.1 C130.1 C152.1 C153.1 C154.1 C164.1 C166.1 C167.1 C168.1 C171.1 C180.1 FB4.1 J4.3 J5.3 L6.2 P9.3 P9.4 P10.4(VDD) Q4.2(E) R3.1 R55.1 R56.1 R57.1 R58.1 R59.1 R60.1 R61.1 R62.1 R63.1 R64.1 R65.1 R66.1 R67.1 R68.1 R69.1 R70.1 R101.1 R102.1 R103.1 R104.1 R105.1 R106.1 R107.1 R108.1 R109.1 R110.1 R111.1 R132.1 R133.1 R139.1 R142.1 R150.1 R151.1 R152.1 R153.1 R154.1 R155.1 R156.1 R157.2 R172.1 R173.1 R177.1 R178.1 R188.1 R192.1 R193.1 R209.1 R210.1 R217.2 R218.2 U7.4(VCC) U13.C6(VCCQ4) U13.E6(VCC3) U13.F5(VCC2) U13.J10(VCC0) U13.K9(VCC1) U13.M4(VCCQ5) U13.N4(VCCQ3) U13.P3(VCCQ1) U13.P5(VCCQ2) U17.5(VCC) U18.1(IN1) U18.2(IN2) U18.4(BIAS) U19.1(IN) ; also on sheet 9 10 11
VDD_3V3_EN: C35.1 R54.2 R194.2 R195.2 R197.1 U20.4(EN)
VDD_3V3_PG: R192.2 U20.6(PG)
VDD_5V: C1.1 C175.1 P9.5 P9.6 R12.1 R168.1 U4.3(VIN1)
VDD_ADC: P9.32 ; also on sheet 10 11
VDD_CORE: C8.1 L2.2 U2.2(FB_B2) ; also on sheet 11
VDD_MPU: C3.1 C15.1 L1.2 U2.8(FB_B1) ; also on sheet 11
VDDS: Q4.3(C) R219.1 U24.3(ANODE) ; also on sheet 11
VDDS_DDR: C10.1 C107.1 C108.1 C109.1 C110.1 C111.1 C112.1 C113.1 C114.1 C115.1 C116.1 C117.1 C118.1 C119.1 C120.1 C121.1 C122.1 L3.2 R97.1 R98.1 U2.18(FB_B3) U12.A1(VDDQ1) U12.A8(VDDQ2) U12.B2(VDD1) U12.C1(VDDQ3) U12.C9(VDDQ4) U12.D2(VDDQ5) U12.D9(VDD9) U12.E9(VDDQ7) U12.F1(VDDQ8) U12.G7(VDD2) U12.H2(VDDQ9) U12.H9(VDDQ10) U12.K2(VDD4) U12.K8(VDD5) U12.N1(VDD6) U12.N9(VDD7) U12.R1(VDD8) U12.R9(VDD3) ; also on sheet 11
AIN0: P9.39 ; also on sheet 10
AIN1: P9.40 ; also on sheet 10
AIN2: P9.37 ; also on sheet 10
AIN3: P9.38 ; also on sheet 10
AIN4: P9.33 ; also on sheet 10
AIN5: P9.36 ; also on sheet 10
AIN6: P9.35 ; also on sheet 10
BOOT2: D7.2 R75.2 S2.1(A1) S2.3(A2)
CLKOUT2: P9.41 ; also on sheet 9
DDR_A0: U12.N3(A0) ; also on sheet 9
DDR_A1: U12.P7(A1) ; also on sheet 9
DDR_A2: U12.P3(A2) ; also on sheet 9
DDR_A3: U12.N2(A3) ; also on sheet 9
DDR_A4: U12.P8(A4) ; also on sheet 9
DDR_A5: U12.P2(A5) ; also on sheet 9
DDR_A6: U12.R8(A6) ; also on sheet 9
DDR_A7: U12.R2(A7) ; also on sheet 9
DDR_A8: U12.T8(A8) ; also on sheet 9
DDR_A9: U12.R3(A9) ; also on sheet 9
DDR_A10: U12.L7(A10) ; also on sheet 9
DDR_A11: U12.R7(A11) ; also on sheet 9
DDR_A12: U12.N7(A12) ; also on sheet 9
DDR_A13: U12.T3(A13) ; also on sheet 9
DDR_A14: U12.T7(A14) ; also on sheet 9
DDR_A15: U12.M7(A15) ; also on sheet 9
DDR_BA0: U12.M2(BA0) ; also on sheet 9
DDR_BA1: U12.N8(BA1) ; also on sheet 9
DDR_BA2: U12.M3(BA2) ; also on sheet 9
DDR_CASn: U12.K3(CASn) ; also on sheet 9
DDR_CKE: R96.2 U12.K9(CKE) ; also on sheet 9
DDR_CLK: U12.J7(CK) ; also on sheet 9
DDR_CLKn: U12.K7(CKn) ; also on sheet 9
DDR_CSn: U12.L2(CSn) ; also on sheet 9
DDR_D0: U12.E3(DQ0) ; also on sheet 9
DDR_D1: U12.F7(DQ1) ; also on sheet 9
DDR_D2: U12.F2(DQ2) ; also on sheet 9
DDR_D3: U12.F8(DQ3) ; also on sheet 9
DDR_D4: U12.H3(DQ4) ; also on sheet 9
DDR_D5: U12.H8(DQ5) ; also on sheet 9
DDR_D6: U12.G2(DQ6) ; also on sheet 9
DDR_D7: U12.H7(DQ7) ; also on sheet 9
DDR_D8: U12.D7(DQ8) ; also on sheet 9
DDR_D9: U12.C3(DQ9) ; also on sheet 9
DDR_D10: U12.C8(DQ10) ; also on sheet 9
DDR_D11: U12.C2(DQ11) ; also on sheet 9
DDR_D12: U12.A7(DQ12) ; also on sheet 9
DDR_D13: U12.A2(DQ13) ; also on sheet 9
DDR_D14: U12.B8(DQ14) ; also on sheet 9
DDR_D15: U12.A3(DQ15) ; also on sheet 9
DDR_DQM0: U12.E7(LDM) ; also on sheet 9
DDR_DQM1: U12.D3(UDM) ; also on sheet 9
DDR_DQS0: U12.F3(LDQS) ; also on sheet 9
DDR_DQS1: U12.C7(UDQS) ; also on sheet 9
DDR_DQSN0: U12.G3(LDQSn) ; also on sheet 9
DDR_DQSN1: U12.B7(UDQSn) ; also on sheet 9
DDR_ODT: U12.K1(ODT) ; also on sheet 9
DDR_RASn: U12.J3(RASn) ; also on sheet 9
DDR_RESETn: R97.2 R206.2 U12.T2(RESET#) ; also on sheet 9
DDR_VREF: C123.1 C124.1 R98.2 R100.1 U12.H1(VREF_DQ) U12.M8(VREF_CA) ; also on sheet 9
DDR_WEn: U12.L3(WEn) ; also on sheet 9
EHRPWM1A: P9.14 ; also on sheet 9
EHRPWM1B: P9.16 ; also on sheet 9
EHRPWM2A: P8.19 ; also on sheet 9
EHRPWM2B: P8.13 ; also on sheet 9
eMMC_RSTn: R111.2 U13.K5(~{RST}) ; also on sheet 9
eMMC_VCCI: C125.1 U13.C2(VCCI)
ETH_INT/GPIO3_1: R117.2 U6.44(INT#/PWDN#) ; also on sheet 10
ETH_RST/GPIO1_8: R132.2 U17.2(B) ; also on sheet 10
GPIO0_7: P9.42 ; also on sheet 10
GPIO0_26: P8.14 ; also on sheet 9
GPIO0_27: P8.17 ; also on sheet 9
GPIO1_12: P8.12 ; also on sheet 9
GPIO1_13: P8.11 ; also on sheet 9
GPIO1_14: P8.16 ; also on sheet 9
GPIO1_15: P8.15 ; also on sheet 9
GPIO1_16: P9.15 ; also on sheet 9
GPIO1_17: P9.23 ; also on sheet 9
GPIO1_28: P9.12 ; also on sheet 9
GPIO1_29: P8.26 ; also on sheet 9
GPIO2_1: P8.18 ; also on sheet 9
GPIO3_19: P9.27 ; also on sheet 10
GPIO3_21: P9.25 ; also on sheet 9 10
GRN+: D11.2 P5.11(GRN+) R135.1
I2C0_SCL: R9.1 U7.1(SCL) ; also on sheet 10
I2C0_SDA: R10.1 U7.3(SDA) ; also on sheet 10
I2C1_SCL: P9.17 R209.2 ; also on sheet 10
I2C1_SDA: P9.18 R210.2 ; also on sheet 10
I2C2_SCL: D22.2 J4.1 P9.19 R177.2 ; also on sheet 10
I2C2_SDA: D21.2 J4.2 P9.20 R178.2 ; also on sheet 10
INTn: R8.1 U2.15(nINT)
LCD_DATA0: P8.45 R70.2 R95.1 ; also on sheet 10
LCD_DATA1: P8.46 R69.2 R94.1 ; also on sheet 10
LCD_DATA2: P8.43 R68.2 R75.1 R93.1 ; also on sheet 10
LCD_DATA3: P8.44 R67.2 R92.1 ; also on sheet 10
LCD_DATA4: P8.41 R66.2 R91.1 ; also on sheet 10
LCD_DATA5: P8.42 R65.2 R90.1 ; also on sheet 10
LCD_DATA6: P8.39 R64.2 R89.1 ; also on sheet 10
LCD_DATA7: P8.40 R63.2 R88.1 ; also on sheet 10
LCD_DATA8: P8.37 R62.2 R87.1 ; also on sheet 10
LCD_DATA9: P8.38 R61.2 R86.1 ; also on sheet 10
LCD_DATA10: P8.36 R60.2 R85.1 ; also on sheet 10
LCD_DATA11: P8.34 R59.2 R84.1 ; also on sheet 10
LCD_DATA12: P8.35 R58.2 R83.1 ; also on sheet 10
LCD_DATA13: P8.33 R57.2 R82.1 ; also on sheet 10
LCD_DATA14: P8.31 R56.2 R81.1 ; also on sheet 10
LCD_DATA15: P8.32 R55.2 R80.1 ; also on sheet 10
LCD_DE: P8.30 ; also on sheet 10
LCD_HSYNC: P8.29 ; also on sheet 10
LCD_PCLK: P8.28 ; also on sheet 10
LCD_VSYNC: P8.27 ; also on sheet 10
LEDAA: D2.1(A) R72.2
LEDAC: D2.2(C) Q1.6(3)
LEDBA: D3.1(A) R73.2
LEDBC: D3.2(C) Q1.3
LEDCA: D4.1(A) R74.2
LEDCC: D4.2(C) Q2.6(3)
LEDDA: D5.1(A) R71.2
LEDDC: D5.2(C) Q2.3
LX_B1: L1.1 U2.11(LX_B1)
LX_B2: L2.1 U2.23(LX_B2)
LX_B3: L3.1 U2.21(LX_B3)
MDIO_CLK: U6.16(MDC) ; also on sheet 10
MDIO_DATA: R172.2 U6.17(MDIO) ; also on sheet 10
MMC0_CD: P10.10(SW_B) R157.1 ; also on sheet 9 10
MMC0_CLKO: R16.1 ; also on sheet 9
MMC0_CMD: R15.1 ; also on sheet 9
MMC0_DAT0: R21.1 ; also on sheet 9
MMC0_DAT1: R31.1 ; also on sheet 9
MMC0_DAT2: R2.1 ; also on sheet 9
MMC0_DAT3: R13.1 ; also on sheet 9
MMC1_CLK: P8.21 R110.2 U13.M6(CLK) ; also on sheet 9
MMC1_CMD: P8.20 R109.2 U13.M5(CMD) ; also on sheet 9
MMC1_DAT0: P8.25 R101.2 U13.A3(DAT0) ; also on sheet 9
MMC1_DAT1: P8.24 R102.2 U13.A4(DAT1) ; also on sheet 9
MMC1_DAT2: P8.5 R103.2 U13.A5(DAT2) ; also on sheet 9
MMC1_DAT3: P8.6 R104.2 U13.B2(DAT3) ; also on sheet 9
MMC1_DAT4: P8.23 R105.2 U13.B3(DAT4) ; also on sheet 9
MMC1_DAT5: P8.22 R106.2 U13.B4(DAT5) ; also on sheet 9
MMC1_DAT6: P8.3 R107.2 U13.B5(DAT6) ; also on sheet 9
MMC1_DAT7: P8.4 R108.2 U13.B6(DAT7) ; also on sheet 9
MODE/STBY: R6.2 R11.1 U2.1(MODE/STBY)
nRSTOUT: R7.1 U2.17(nRSTOUT)
PHY_CLK_OUT: TP12.1(TP) U6.18(CLK_OUT)
PHY_GPIO0: R124.2 R130.1 U6.39(GPIO_0)
PHY_GPIO1: R125.2 R131.1 U6.40(GPIO_1)
PHY_LED0: R120.2 R126.1 R136.2 U6.47(LED_0)
PHY_LED1: R121.2 R127.1 R137.2 U6.46(LED_1)
PHY_LED2: R122.2 R128.1 R135.2 U6.45(LED_2)
PHY_RBIAS: R118.1 U6.12(RBIAS)
PHY_RST#: C185.1 R133.2 U6.43(RESET#) U17.4(Y)
PHY_TD_A_M: P5.3(TD1-) U1.2(CH2) U1.9(NC2) U6.2(TD_M_A)
PHY_TD_A_P: P5.2(TD1+) U1.1(CH1) U1.10(NC1) U6.1(TD_P_A)
PHY_TD_B_M: P5.5(TD2-) U1.5(CH4) U1.6(NC4) U6.5(TD_M_B)
PHY_TD_B_P: P5.4(TD2+) U1.4(CH3) U1.7(NC3) U6.4(TD_P_B)
PHY_TD_C_M: P5.7(TD3-) U6.8(TD_M_C) U14.2(CH2) U14.9(NC2)
PHY_TD_C_P: P5.6(TD3+) U6.7(TD_P_C) U14.1(CH1) U14.10(NC1)
PHY_TD_D_M: P5.9(TD4-) U6.11(TD_M_D) U14.5(CH4) U14.6(NC4)
PHY_TD_D_P: P5.8(TD4+) U6.10(TD_P_D) U14.4(CH3) U14.7(NC3)
PHY_VDD_1V: C147.1 C148.1 C149.1 C150.1 C156.1 C157.1 C160.1 C161.1 C162.1 C163.1 FB6.2 U6.6(VDD1P0[1]) U6.24(VDD1P0[2]) U6.31(VDD1P0[3]) U6.42(VDD1P0[4])
PHY_VDDA_1V8_1: TP10.1(TP) U6.13(VDDA1P8[1])
PHY_VDDA_1V8_2: TP11.1(TP) U6.48(VDDA1P8[2])
PHY_VDDA_2V5: C140.1 C141.1 C142.1 C143.1 C144.1 C145.1 FB5.2 U6.3(VDDA2P5[1]) U6.9(VDDA2P5[2])
PHY_VDDIO_3V3: C132.1 C133.1 C134.1 C135.1 C136.1 C137.1 C138.1 C139.1 FB4.2 R117.1 R120.1 R121.1 R122.1 R123.1 R124.1 R125.1 U6.19(VDDIO1) U6.30(VDDIO2) U6.41(VDDIO3)
PHY_XI: C17.1 C27.1 U6.15(XI) X1.1
PHY_XO: R119.1 U6.14(XO)
PHY_XO_R: C131.1 R119.2 X1.3
PMIC_EN: R4.2 R175.2 U2.19(EN/PB/VSENSE)
PMIC_I2C_SCL: R9.2 U2.14(SCL)
PMIC_I2C_SDA: R10.2 U2.13(SDA)
PMIC_INT: R3.2 R8.2 ; also on sheet 9
PMIC_POWR_EN: R175.1 ; also on sheet 10
PMIC_RSTOUTn: C36.1 U9.4(Y) ; also on sheet 9
PR1: R12.2 R174.1 U4.4(PR1)
PWR_BUT: P9.9 ; also on sheet 10
PWR_ST/GPIO1_9: R176.2 ; also on sheet 10
RGMII1_RCLK: R115.1 ; also on sheet 10
RGMII1_RCTL: R116.1 ; also on sheet 10
RGMII1_RD0: R35.1 ; also on sheet 10
RGMII1_RD1: R112.1 ; also on sheet 10
RGMII1_RD2: R113.1 ; also on sheet 10
RGMII1_RD3: R114.1 ; also on sheet 10
RGMII1_TCTL: R171.1 ; also on sheet 10
RGMII1_TD0: R148.1 ; also on sheet 10
RGMII1_TD1: R149.1 ; also on sheet 10
RGMII1_TD2: R158.1 ; also on sheet 10
RGMII1_TD3: R166.1 ; also on sheet 10
RGMII1_TXCLK: R34.1 ; also on sheet 10
RMII1_REFCLK: C17.2 ; also on sheet 10
RSTOUTn: C20.1 D25.2 R1.2 R7.2 U9.2(A)
RX_CLK: R115.2 U6.32(RX_CLK)
RX_CTRL: R116.2 R123.2 R129.1 U6.38(RX_CTRL)
RX_D0: R35.2 U6.33(RX_D0)
RX_D1: R112.2 U6.34(RX_D1)
RX_D2: R113.2 U6.35(RX_D2)
RX_D3: R114.2 U6.36(RX_D3)
SD_CLK: C5.1 P10.5(CLOCK) R16.2 R152.2
SD_CMD: P10.3(CMD) R15.2 R151.2
SD_DAT0: P10.7(DAT0) R21.2 R153.2
SD_DAT1: P10.8(DAT1) R31.2 R154.2
SD_DAT2: P10.1(DAT2) R2.2 R150.2
SD_DAT3: P10.2(CD/DAT3) R13.2 R155.2
SPI1_CS0: P9.28 ; also on sheet 10
SPI1_D0: P9.29 ; also on sheet 10
SPI1_D1: P9.30 ; also on sheet 10
SPI1_SCLK: P9.31 ; also on sheet 10
SYS_5V: C2.1 C7.1 C9.1 C11.1 C13.1 C176.1 P9.7 P9.8 R4.1 R6.1 R54.1 R71.1 R72.1 R73.1 R74.1 U2.4(VSYS/PVIN_LDO12) U2.12(PVIN_B1) U2.20(PVIN_B3) U2.24(PVIN_B2) U4.2(VOUT_1) U4.7(VOUT_2) U20.3(VIN) ; also on sheet 10
SYS_RESETn: P9.10 U17.1(A) ; also on sheet 9
TIMER4: P8.7 ; also on sheet 9
TIMER5: P8.9 ; also on sheet 9
TIMER6: P8.10 ; also on sheet 9
TIMER7: P8.8 ; also on sheet 9
TPS65214_GPO: R195.1 U2.9(GPO/nWAKEUP)
TX_CLK: R34.2 U6.29(GTX_CLK)
TX_CTRL: R171.2 U6.37(TX_CTRL)
TX_D0: R148.2 U6.28(TX_D0)
TX_D1: R149.2 U6.27(TX_D1)
TX_D2: R158.2 U6.26(TX_D2)
TX_D3: R166.2 U6.25(TX_D3)
UART1_RXD: P9.26 ; also on sheet 10
UART1_TXD: P9.24 ; also on sheet 10
UART2_RXD: D24.2 J5.1 P9.22 ; also on sheet 10
UART2_TXD: D23.2 J5.2 P9.21 ; also on sheet 10
UART4_RXD: P9.11 ; also on sheet 9
UART4_TXD: P9.13 ; also on sheet 9
USB_DC: C146.1 C177.1 U4.6(VIN2) ; also on sheet 10
USR0: Q1.2(5) R76.1 ; also on sheet 9
USR1: Q1.5 R77.1 ; also on sheet 9
USR2: Q2.2(5) R78.1 ; also on sheet 9
USR3: Q2.5 R79.1 ; also on sheet 9
VSEL: R5.1 U2.16(GPIO/VSEL)
WP: R156.2 R189.1 TP4.1(TP) U7.5(WP)
YEL+: D12.2 P5.13(YEL+) R136.1 R137.1
ZQ: R99.1 U12.L8(ZQ)
N22569088: J5.4 R147.2
N22569092: J4.4 R146.2
N23169174: C174.1 R142.2 U19.3(EN)
N23207628: D1.1(A) R188.2
N23386908: Q4.1(B) R217.1 U24.2(CATHODE)
N23386910: R218.1 R219.2 U24.1(REF)
N23671973: R173.2 R176.1 U4.8(ST)
N23672011: R168.2 U4.5(MODE)

Not connected (* = marked no-connect by the designer): P5 10(NC)*; P10 S2(SHD2)*; U6 20(JTAG_CLK)* 21(JTAG_TDO)* 22(JTAG_TMS)* 23(JTAG_TDI)*; U9 1(NC)*; U12 J1(NC1)* J9(NC2)* L1(NC3)* L9(NC4)*; U13 A1(NC11)* A2(NC4)* A7(RFU1)* A8(NC7)* A9(NC18)* A10(NC95)* A11(NC94)* A12(NC93)* A13(NC92)* A14(NC91)* B1(NC90)* B7(NC89)* B8(NC74)* B9(NC53)* B10(NC52)* B11(NC51)* B12(NC50)* B13(NC49)* B14(NC19)* C1(NC34)* C3(NC33)* C5(NC32)* C7(NC31)* C8(NC30)* C9(NC29)* C10(NC25)* C11(NC23)* C12(NC22)* C13(NC21)* C14(NC20)* D1(NC48)* D2(NC46)* D3(NC39)* D4(NC38)* D12(NC37)* D13(NC36)* D14(NC35)* E1(NC1)* E2(NC2)* E3(NC3)* E5(RFU2)* E8(VSF1)* E9(VSF2)* E10(VSF3)* E12(NC12)* E13(NC13)* E14(NC14)* F1(NC15)* F2(NC16)* F3(NC17)* F10(VSF4)* F12(NC26)* F13(NC27)* F14(NC28)* G1(NC88)* G2(NC81)* G3(RFU3)* G10(NC78)* G12(NC40)* G13(NC41)* G14(NC42)* H1(NC43)* H2(NC44)* H3(NC45)* H5(NC47/DS)* H12(NC54)* H13(NC55)* H14(NC56)* J1(NC57)* J2(NC58)* J3(NC59)* J12(NC117)* J13(NC69)* J14(NC70)* K1(NC71)* K2(NC72)* K3(NC73)* K6(RFU4)* K7(RFU5)* K10(VSF6)* K12(NC82)* K13(NC83)* K14(NC84)* L1(NC85)* L2(NC86)* L3(NC87)* L12(NC96)* L13(NC97)* L14(NC98)* M1(NC99)* M2(NC100)* M3(NC101)* M7(NC105)* M8(NC106)* M9(NC107)* M10(NC108)* M11(NC109)* M12(NC110)* M13(NC111)* M14(NC112)* N1(NC113)* N3(NC115)* N6(NC122)* N7(NC118)* N8(NC119)* N9(NC120)* N10(NC75)* N11(NC76)* N12(NC68)* N13(NC67)* N14(NC66)* P1(NC65)* P2(NC64)* P7(NC63)* P8(RFU6)* P9(NC62)* P10(RFU7)* P11(NC104)* P12(NC103)* P13(NC102)* P14(NC116)*

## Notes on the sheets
sheet 1
- Block Diagram
sheet 2
- TABLE OF CONTENTS
- REVISION HISTORY
- PAGE
- CONTENTS
- VER #
- DATE
- REVISION
- DESCRIPTION OF CHANGES
- AUTHOR
- 01
- Title, Revision History
- V1.0
- 10 Jun 2025
- BeagleBone Green Eco_V1.0_SCH_250610
- Initial Release.
- Junqing.Xin
- 02
- Block Diagram
- V1.0
- 14 Aug 2025
- BeagleBone Green Eco_V1.0_SCH_250814
- Page 5: Removed the Wake-Up button (Changed S3 to DNP, R211 from 0R to DNP).
- Junqing.Xin
- 03
- Power Management
- 04
- AM335x 1/3, JTAG
- 05
- AM335x 2/3, USB, UART
- 06
- AM335x 3/3, Power
- 07
- Boot Configuration, LED
- 08
- DDR3 Memory
- 09
- eMMC Flash
- 10
- Gigabit Ethernet
- 11
- Exp Conn, uSD, EEP, Grove
sheet 3
- PMIC
- 1.1V
- 1A
- 1.1V
- 0.4A
- 1.5V
- 0.5A
- Power LED
- PMIC LDO1 for noise sensitive domains like RTC and analog.
- PMIC LDO2 can be used for VDDS/IO.
- 130mA
- 50mA
- RTC Design Note:
- RTC, No RTC Only Mode: R175=DNP, R4=10K.
- I2C 7-bit device address: 0x30 (0b0110000)
- Please note, the net PMIC_POWR_EN is 1.8V from AM335x,
  the SYS_5V is 5V, so Do Not Install R175 and R4 at the same time,
  if not, maybe damage the AM335x !
- Clamping Circuit
- DCDC 5V to 3.3V 1A
- 1.8V
- Review Note:
- 3.3V  1A
- Clamping Circuit For AM335x Power-Down Requirements
- The AM335x datasheet requires that the voltage difference between the
  power rails VDDS (1.8V) and VDDSHVx [1-6] (3.3V) of the AM335x
  processor be less than 2V during the entire power-down sequence.
- This is a clamping circuit between the VDDS and VDD_3V3 outputs of
  the TPS62A01DRL DCDC IC. The clamping circuit is related to
  power down issues (see https://octavosystems.com/osd335x/clamping/
  for more information). This may not be needed in your application
  if the power down conditions do not apply to your application.
- Vout = Vfb x (1 + R193/ R196)
- = 0.6V x (1 + 453K / 100K)
- = 0.6V x 5.53
- = 3.318V
sheet 4
- Boot Configuration
- uSD BOOT Button
- SYS_BOOT2
- 1/0
- SYS_BOOT0
- 0
- SYS_BOOT1
- 0
- SYS_BOOT2
- 1
- SYS_BOOT3
- 1
- SYS_BOOT4
- 1
- SYS_BOOT5
- 1
- SYS_BOOT6
- 0
- SYS_BOOT7
- 0
- SYS_BOOT8
- 0
- SYS_BOOT9
- 0
- SYS_BOOT10
- 0
- SYS_BOOT11
- 0
- SYS_BOOT12
- 0
- SYS_BOOT13
- 0
- SYS_BOOT14
- 1
- SYS_BOOT15
- 0
- User LEDs
- USR0
- USR1
- USR2
- USR3
- 0
- 1
- 0
- 0
- 0
- 0
- 0
- 0
- 0
- 0
- 1
- 1
- 1
- 1
- 0
- 0
sheet 5
- DDR3L SDRAM 512MB
- DDR3L Mode: 1.283V to 1.45V, Type: 1.35V, Max: 249mA.
- DDR3 Mode: 1.425V to 1.575V, Type: 1.5V, Max: 249mA.
sheet 6
- eMMC Flash 16GB
sheet 7
- Gigabit Ethernet
- VDDA2P5:
- MIN=2.375V, TYP=2.5V, MAX=2.625V
- Imax=137mA
- VDD1P0:
- Imax=108mA
- MIN=0.95V, TYP=1V, MAX=1.155V
- TX R* Should close to MPU.
- 100 ohms differential
  trace impedance.
- RX R* Should close to PHY.
- LED0: Link
- JTAG pins can be left
  unconnected if not used
- LED1: Link_1000BT
- LED2: ACT
- PHY address set to 0X00
- ETH Reset
- MAX: 50mA
- LED_0: MODE 1
  Mirror Enable=[0]
  For Enabling Mount R120, R126
- LED1 & LED2: MODE1
  RGMII Clock Skew TX[0:2]=[000]
  ANEG_SEL(Auto-negotiation)=[0]
  PHY_LED[0:2] CANT CONFIGURE IN MODE4
- Autoneg enable. For Disabling
  R123=2.49K, R129=NI
- RGMII Clock Skew RX[0:2]=[000]
- MAX: 137mA
- 3.3V to 2.5V LDO
- 3.3V to 1V LDO
- Imax = 137mA
- MAX: 108mA
- Vfb=0.55V
- Imax = 108mA
- Vfb=0.8V
- Vout = Vfb x (1 + R143 / R144)
- = 0.55V x (1 + 100K / 27.4K)
- = 0.55V x 4.6496
- Vout = Vfb x (1 + R140 / R141)
- = 2.557V
- = 0.8V x (1 + 1.27K / 4.99K)
- = 0.8V x 1.254509
- Layout Note:
  Place 1uF and 0.1uF decoupling capacitors as close as possible to
  component VDD pins, placing the 0.1uF capacitor closest to the pin.
- = 1.0036V
- Ethernet PHY: VDDA2P5=2.5V, Imax=137mA
- Power Consumption: (3.3V-2.5V) * 0.137A = 0.1096W
- Ethernet PHY: VDD1P0=1V, Imax=108mA
- Power Consumption: (3.3V-1V) * 0.108A = 0.2484W
- Thermal Junction-to-ambient: 0.1096W * 176.9°C/W=19.39°C
- Thermal Junction-to-ambient: 0.2484W * 44.2°C/W=10.98°C
- There is no requirement for the sequence of the supplies when operating in two-supply mode.
sheet 8
- CAUTION: USED ON BOARD
- CAUTION: USED ON BOARD
- Expansion Header P8
- Expansion Header P9
- Board ID EEPROM 32Kbit
- Layout Note:
- Place TP1 TP4 To Bottom Side.
- Space = 2.54MM
- Layout Note:
- Add Silkscreen:
- Place R16,C5 Close To MPU.
- uSD Connector
- TP1: GND
- TP4: E_WP
- Priority Power MUX
- MAX: 6V
- MIN: 4V
- Supply 1: VDD_5V, From the P9 Header.
  Supply 2: USB_DC, From the USB Type C.
- Grove Connector
- Output Current Limit: 4A
- Prioritizes Supply 1 when present, and quickly
  switches to Supply 2 when Supply 1 decreases
  to less than 4 V.
- Vref=1V
- Priority Supervisor (PR1):
  VIN1_MIN =(R12+R174) * Vref / R174
                   =(30K+10K) * 1V / 10K
                   =4V
- MAX: 6V
